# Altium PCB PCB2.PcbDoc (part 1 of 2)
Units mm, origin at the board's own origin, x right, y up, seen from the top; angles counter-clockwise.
Board outline 159.99 x 100 mm, 12 copper layers (TopLayer, VCC, GROUND, MidLayer1, MidLayer2, MidLayer3, MidLayer4, MidLayer5, MidLayer6, MidLayer7, MidLayer8, BottomLayer); 300 components, 468 nets, 2269 pads, 42 vias.
Unrouted connection lines stored in the file: 456.
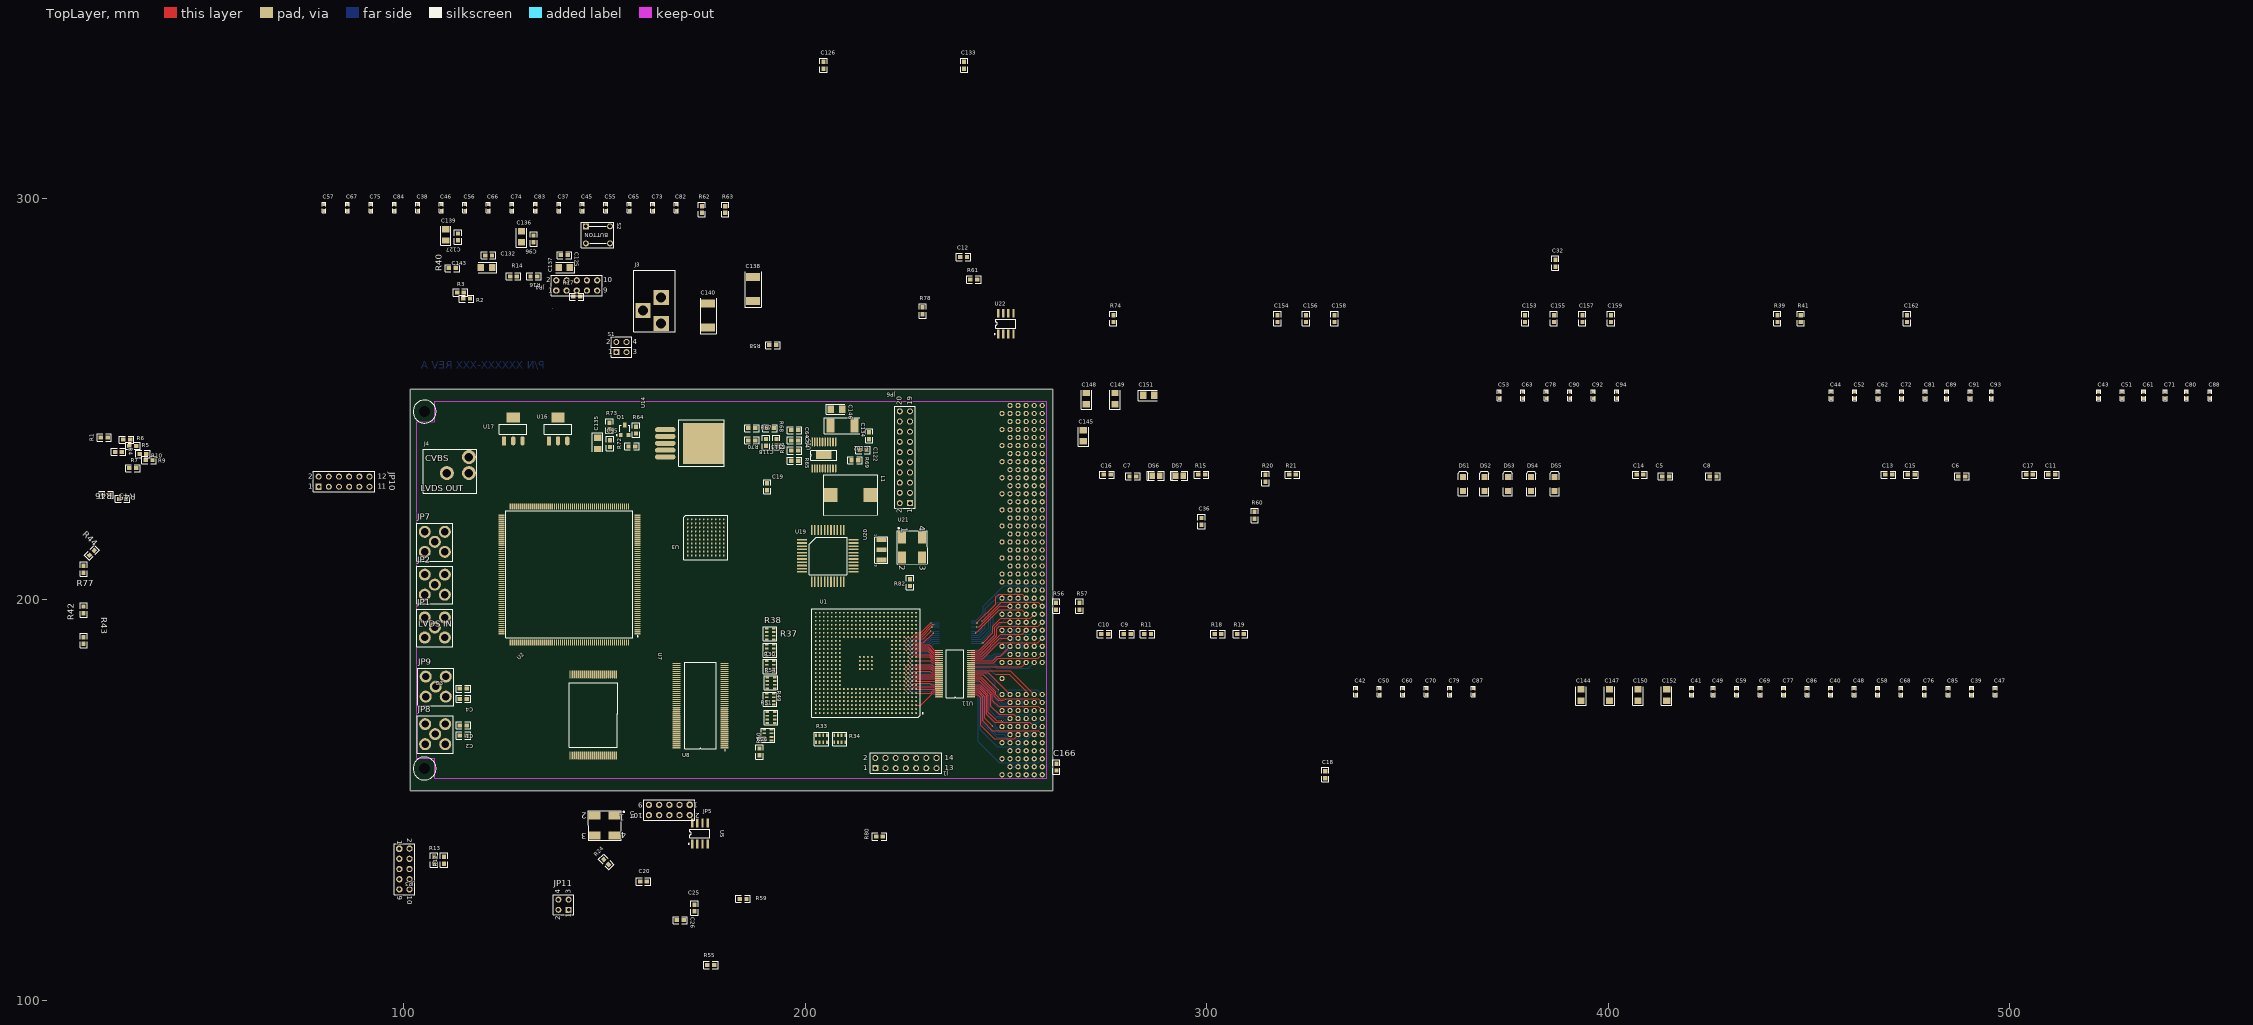
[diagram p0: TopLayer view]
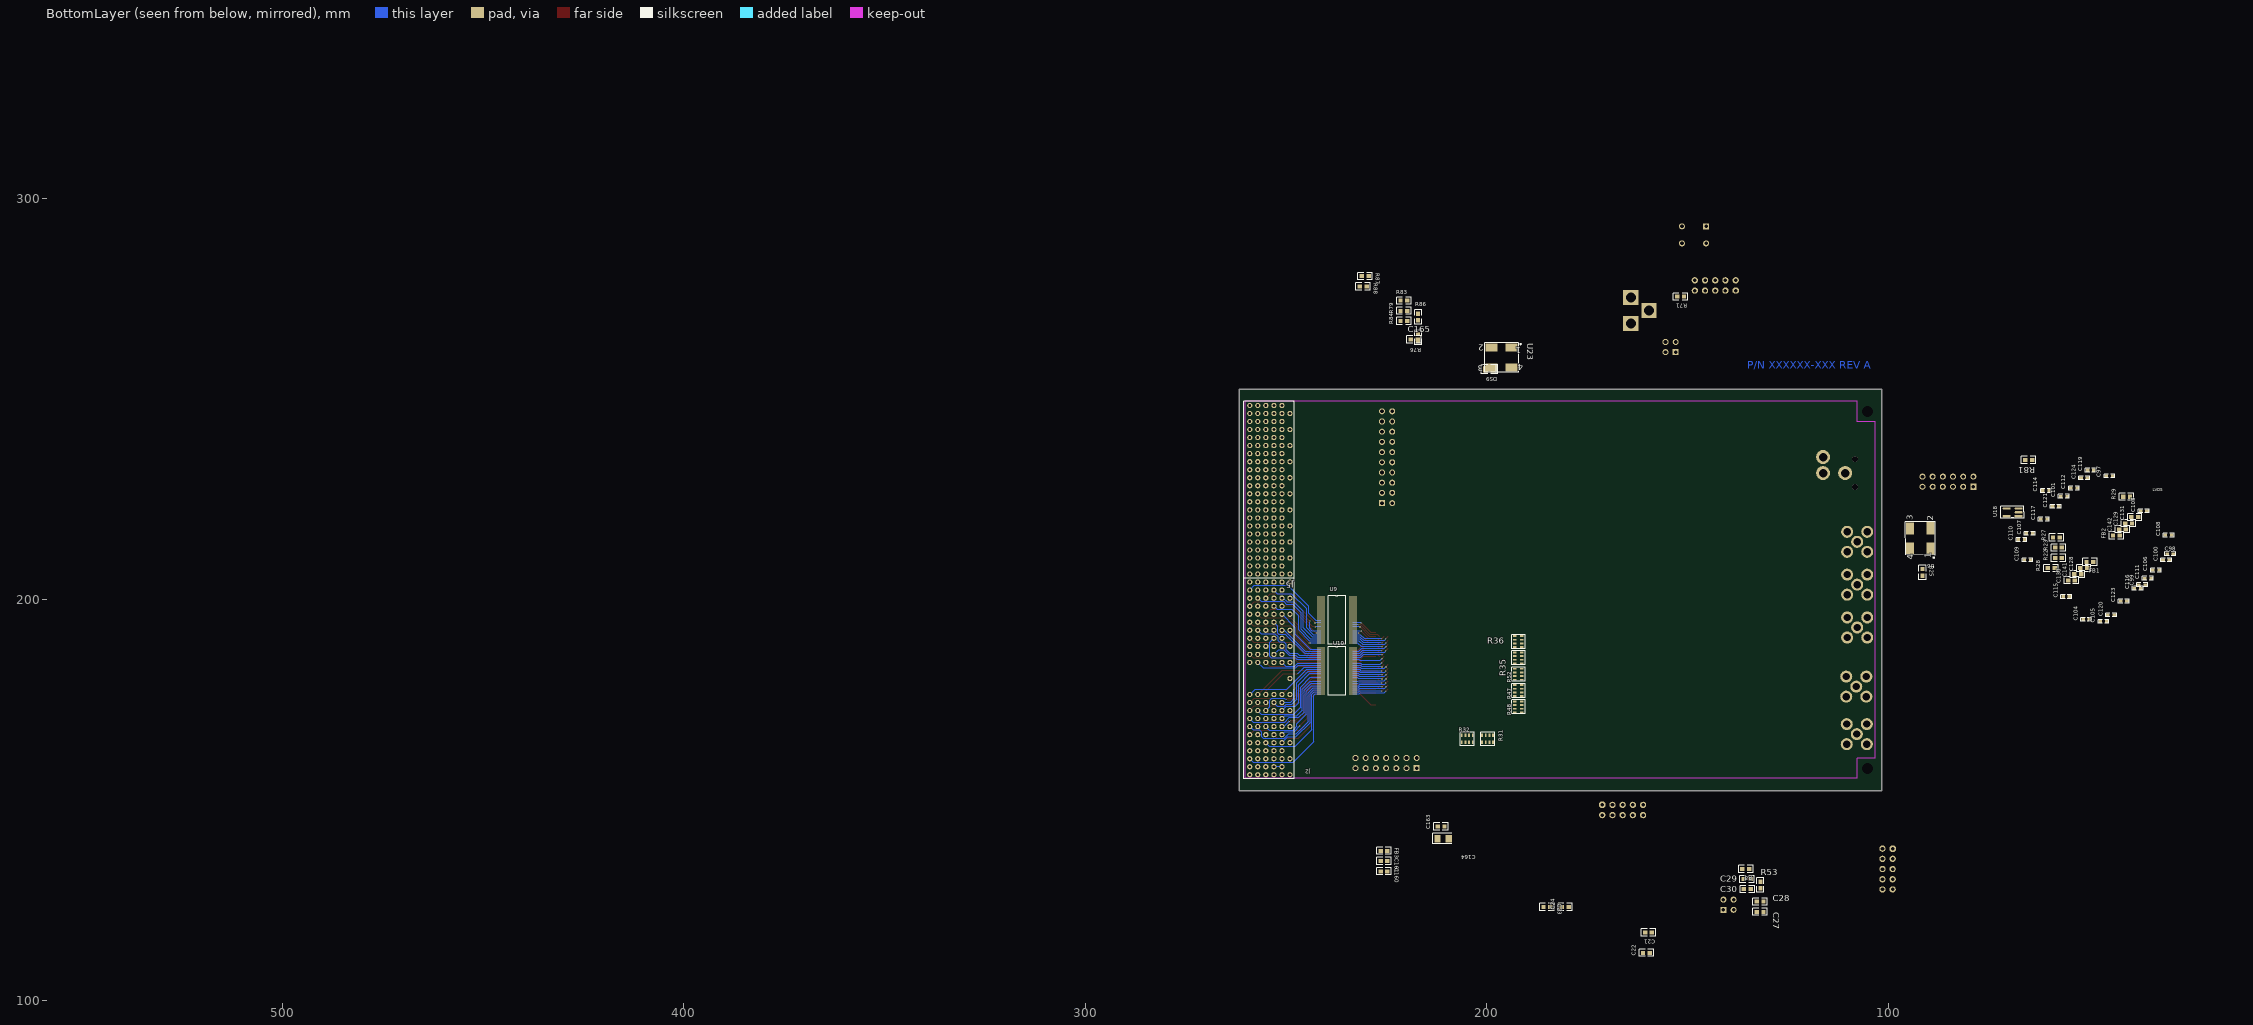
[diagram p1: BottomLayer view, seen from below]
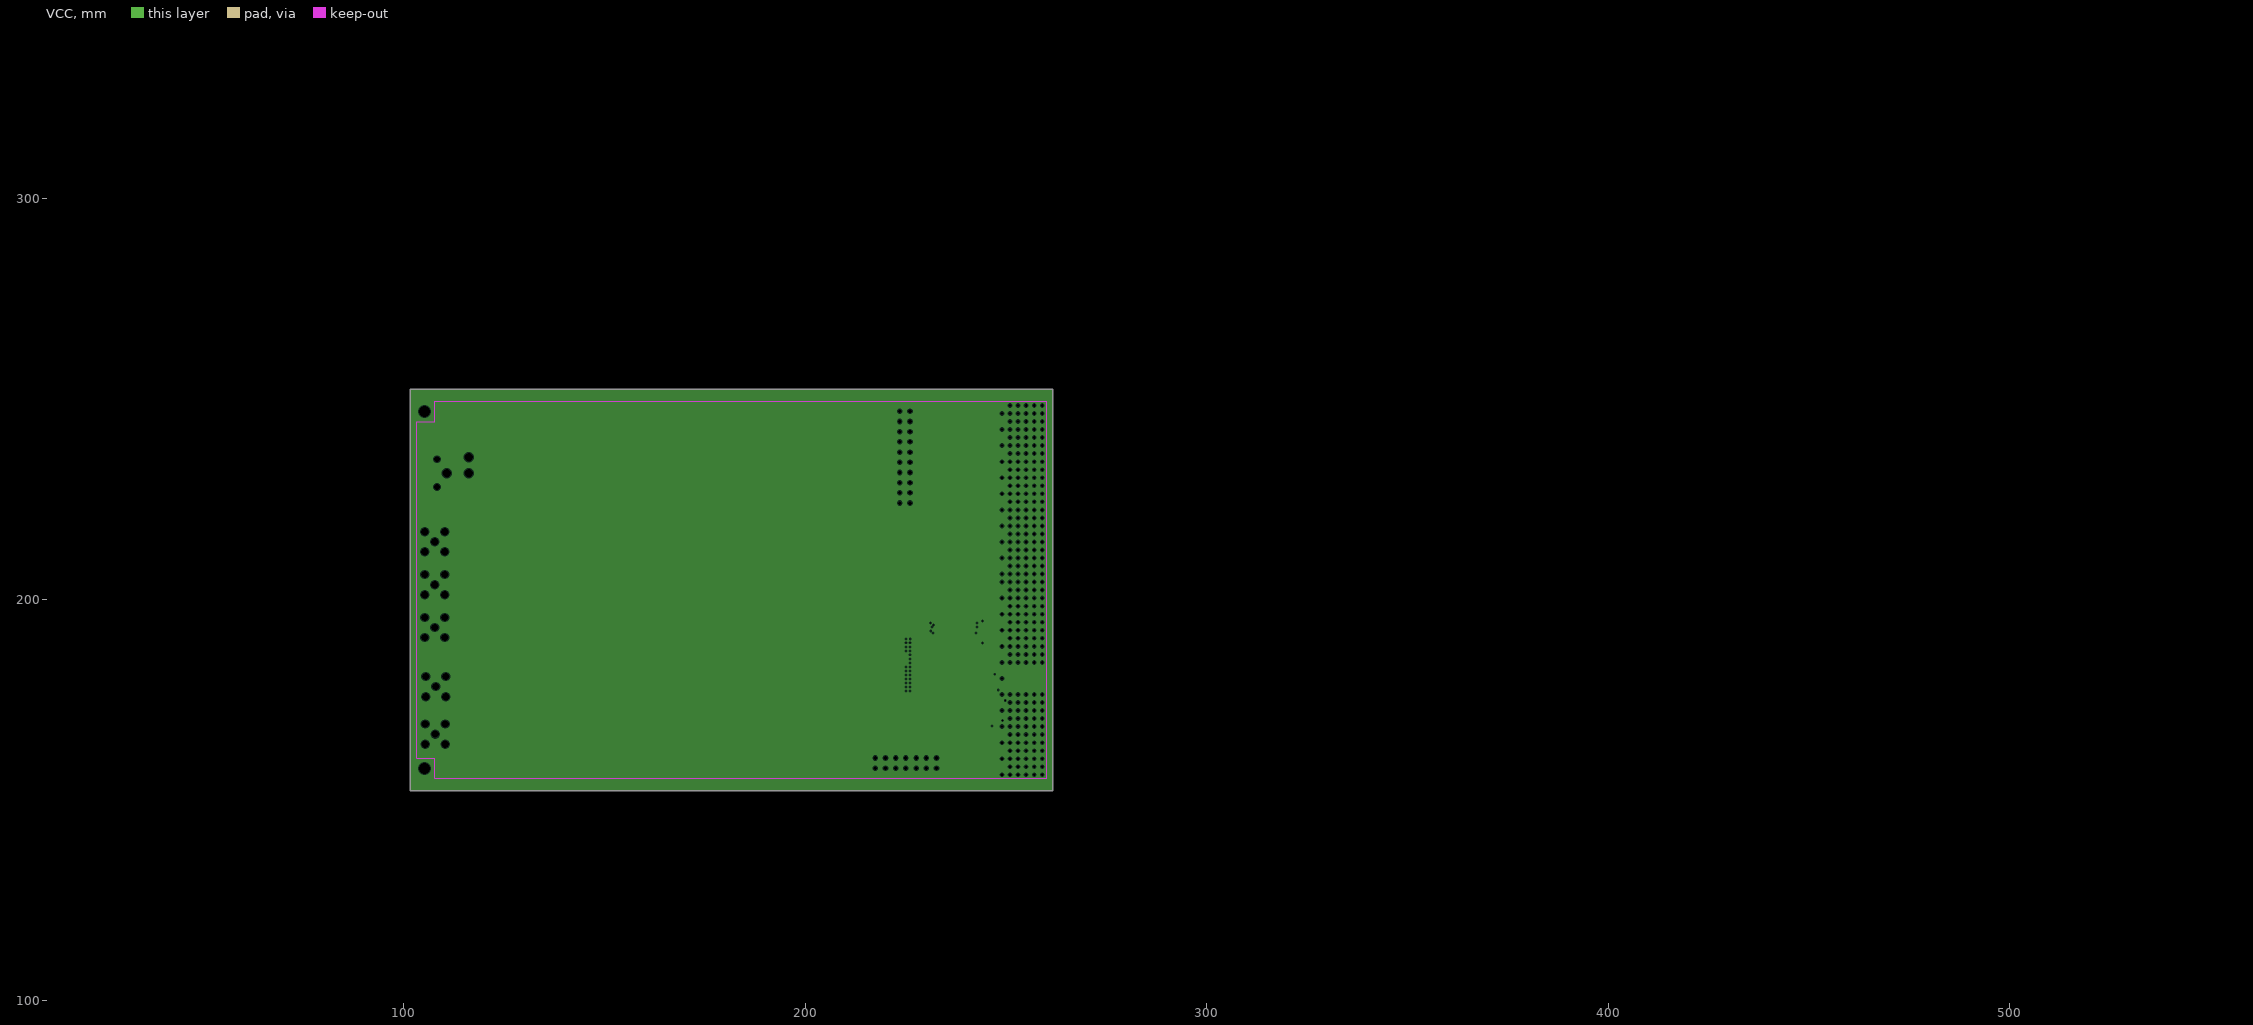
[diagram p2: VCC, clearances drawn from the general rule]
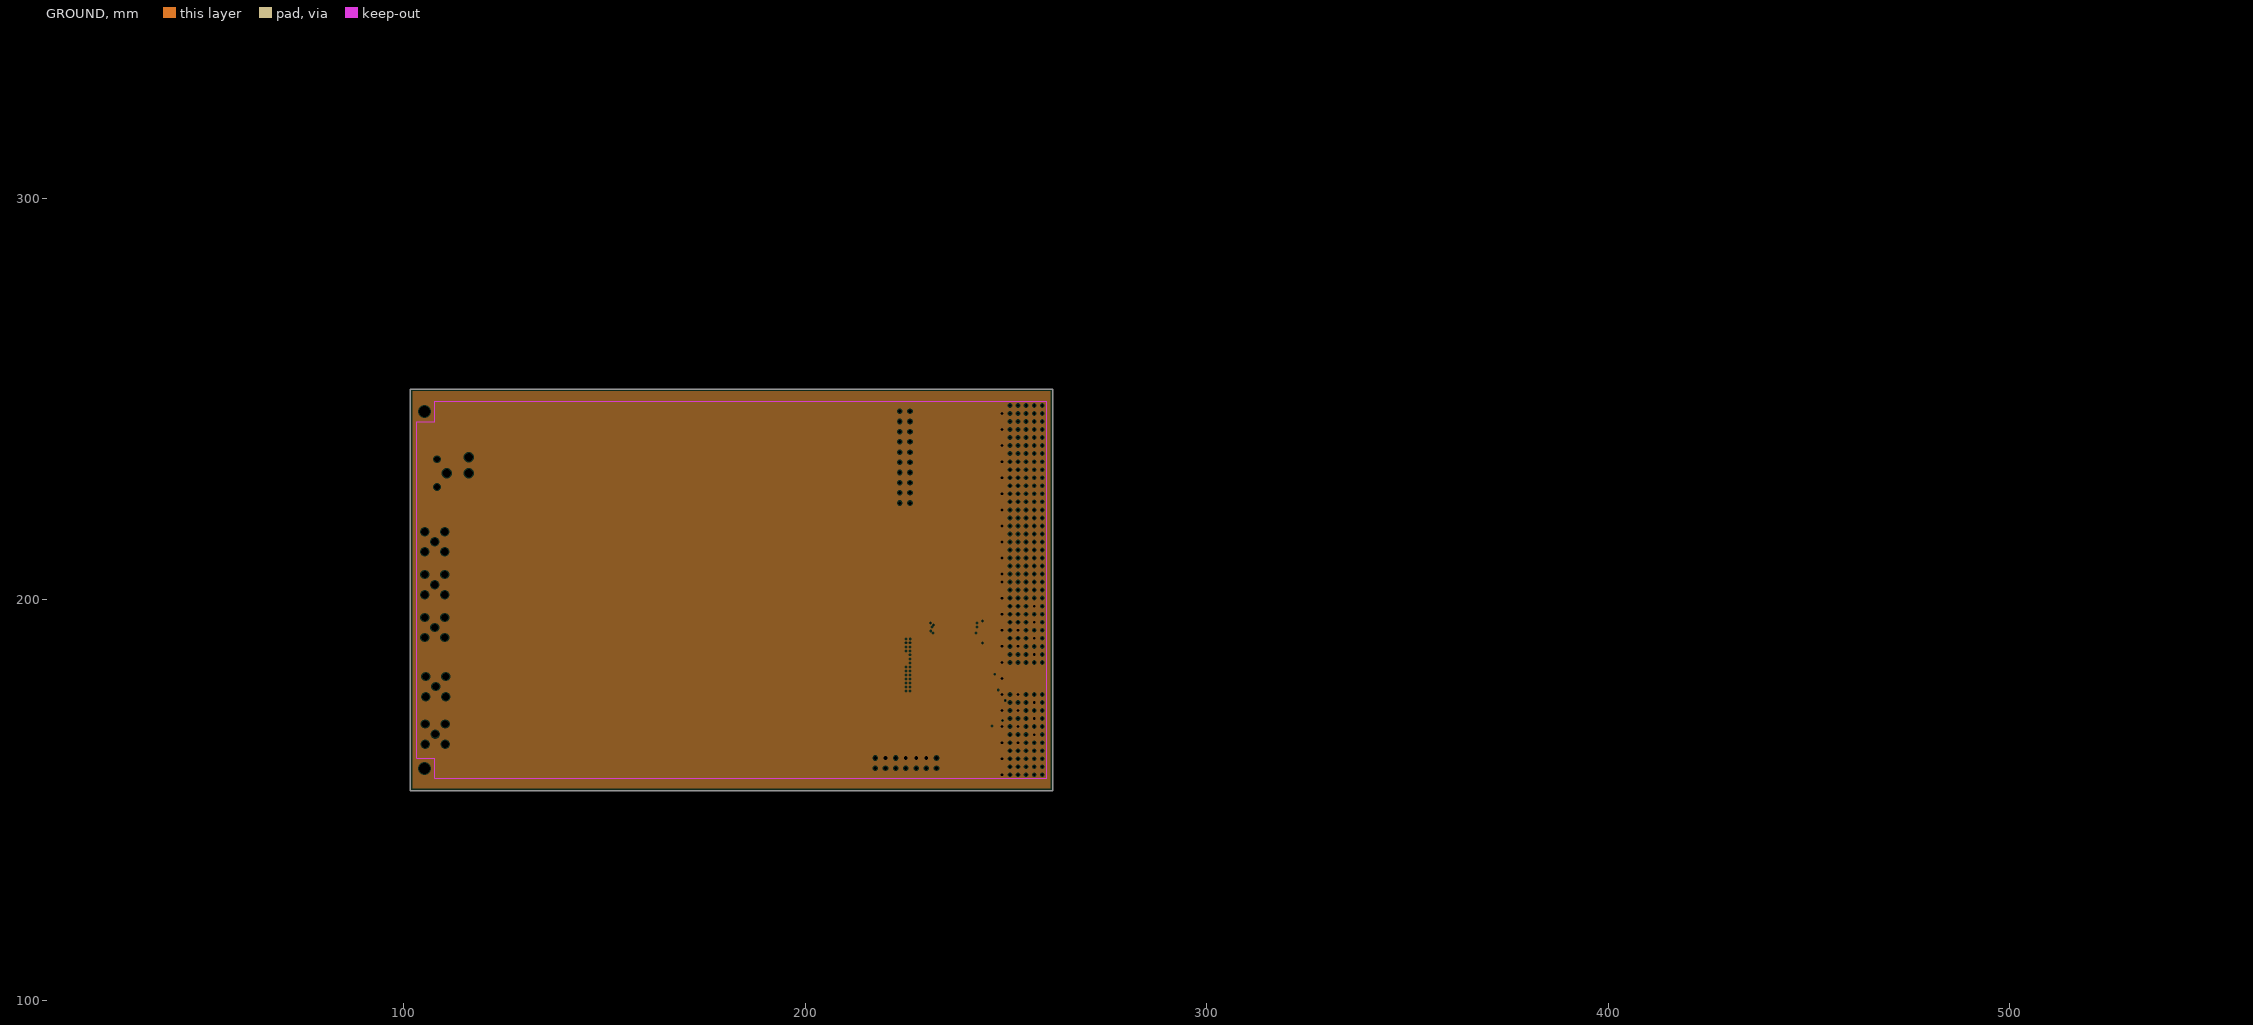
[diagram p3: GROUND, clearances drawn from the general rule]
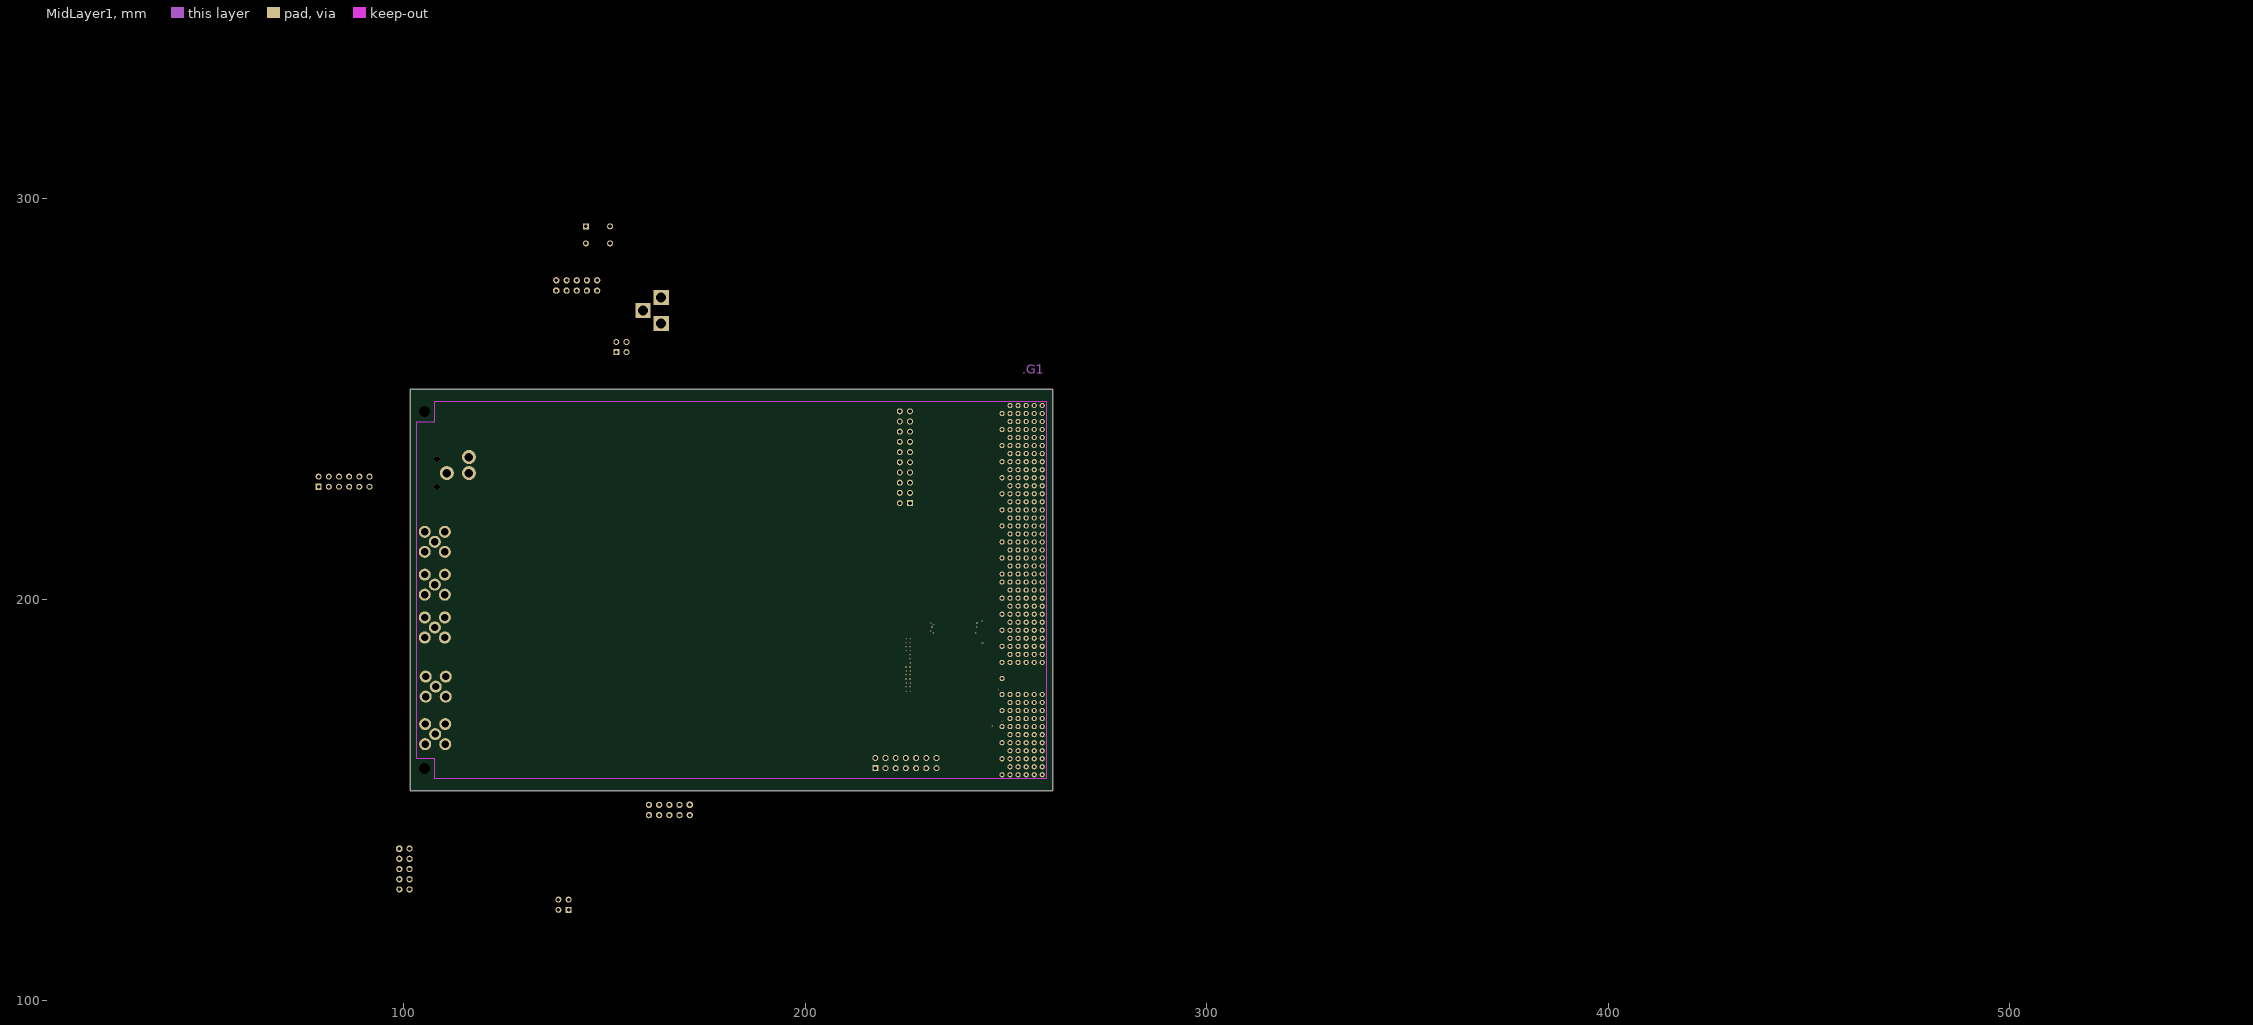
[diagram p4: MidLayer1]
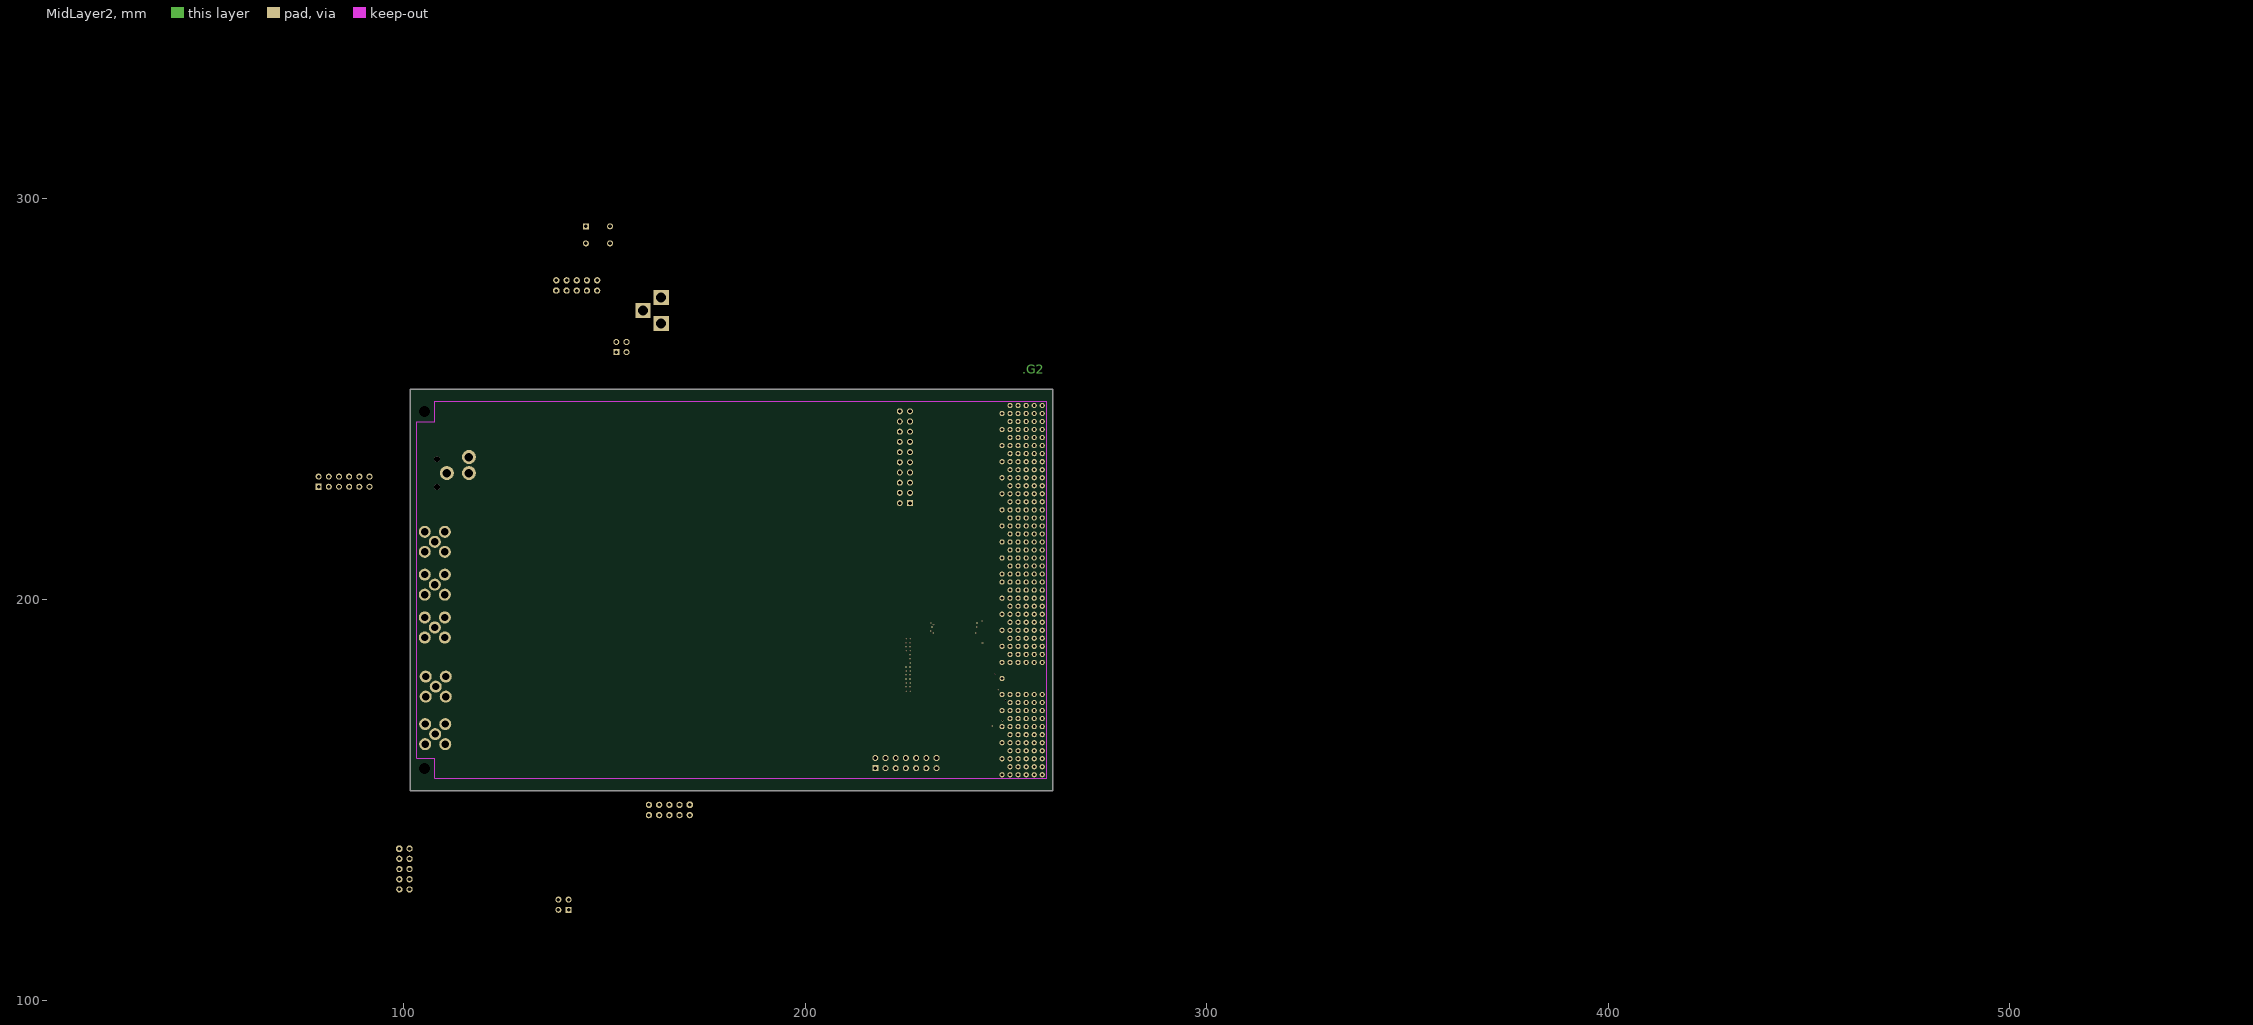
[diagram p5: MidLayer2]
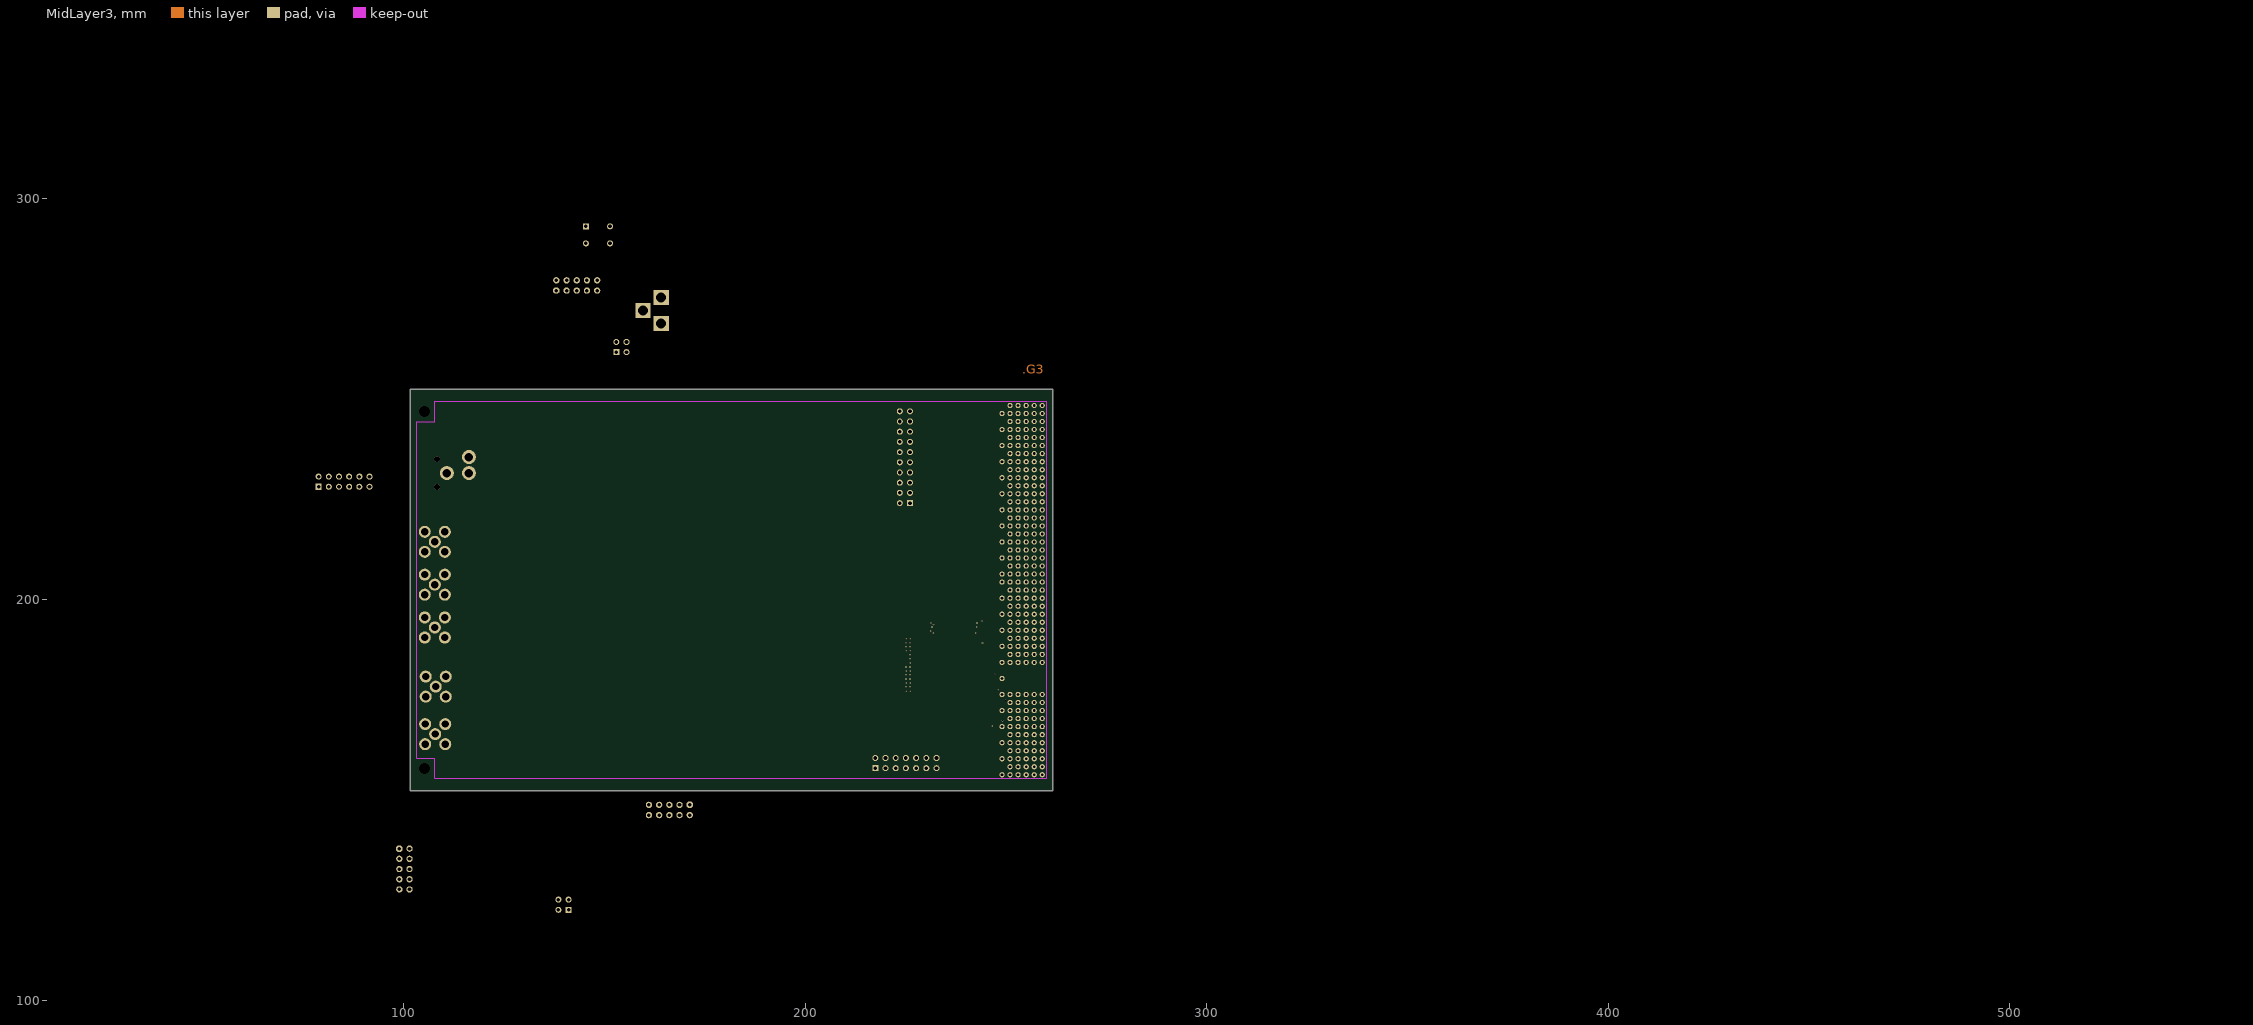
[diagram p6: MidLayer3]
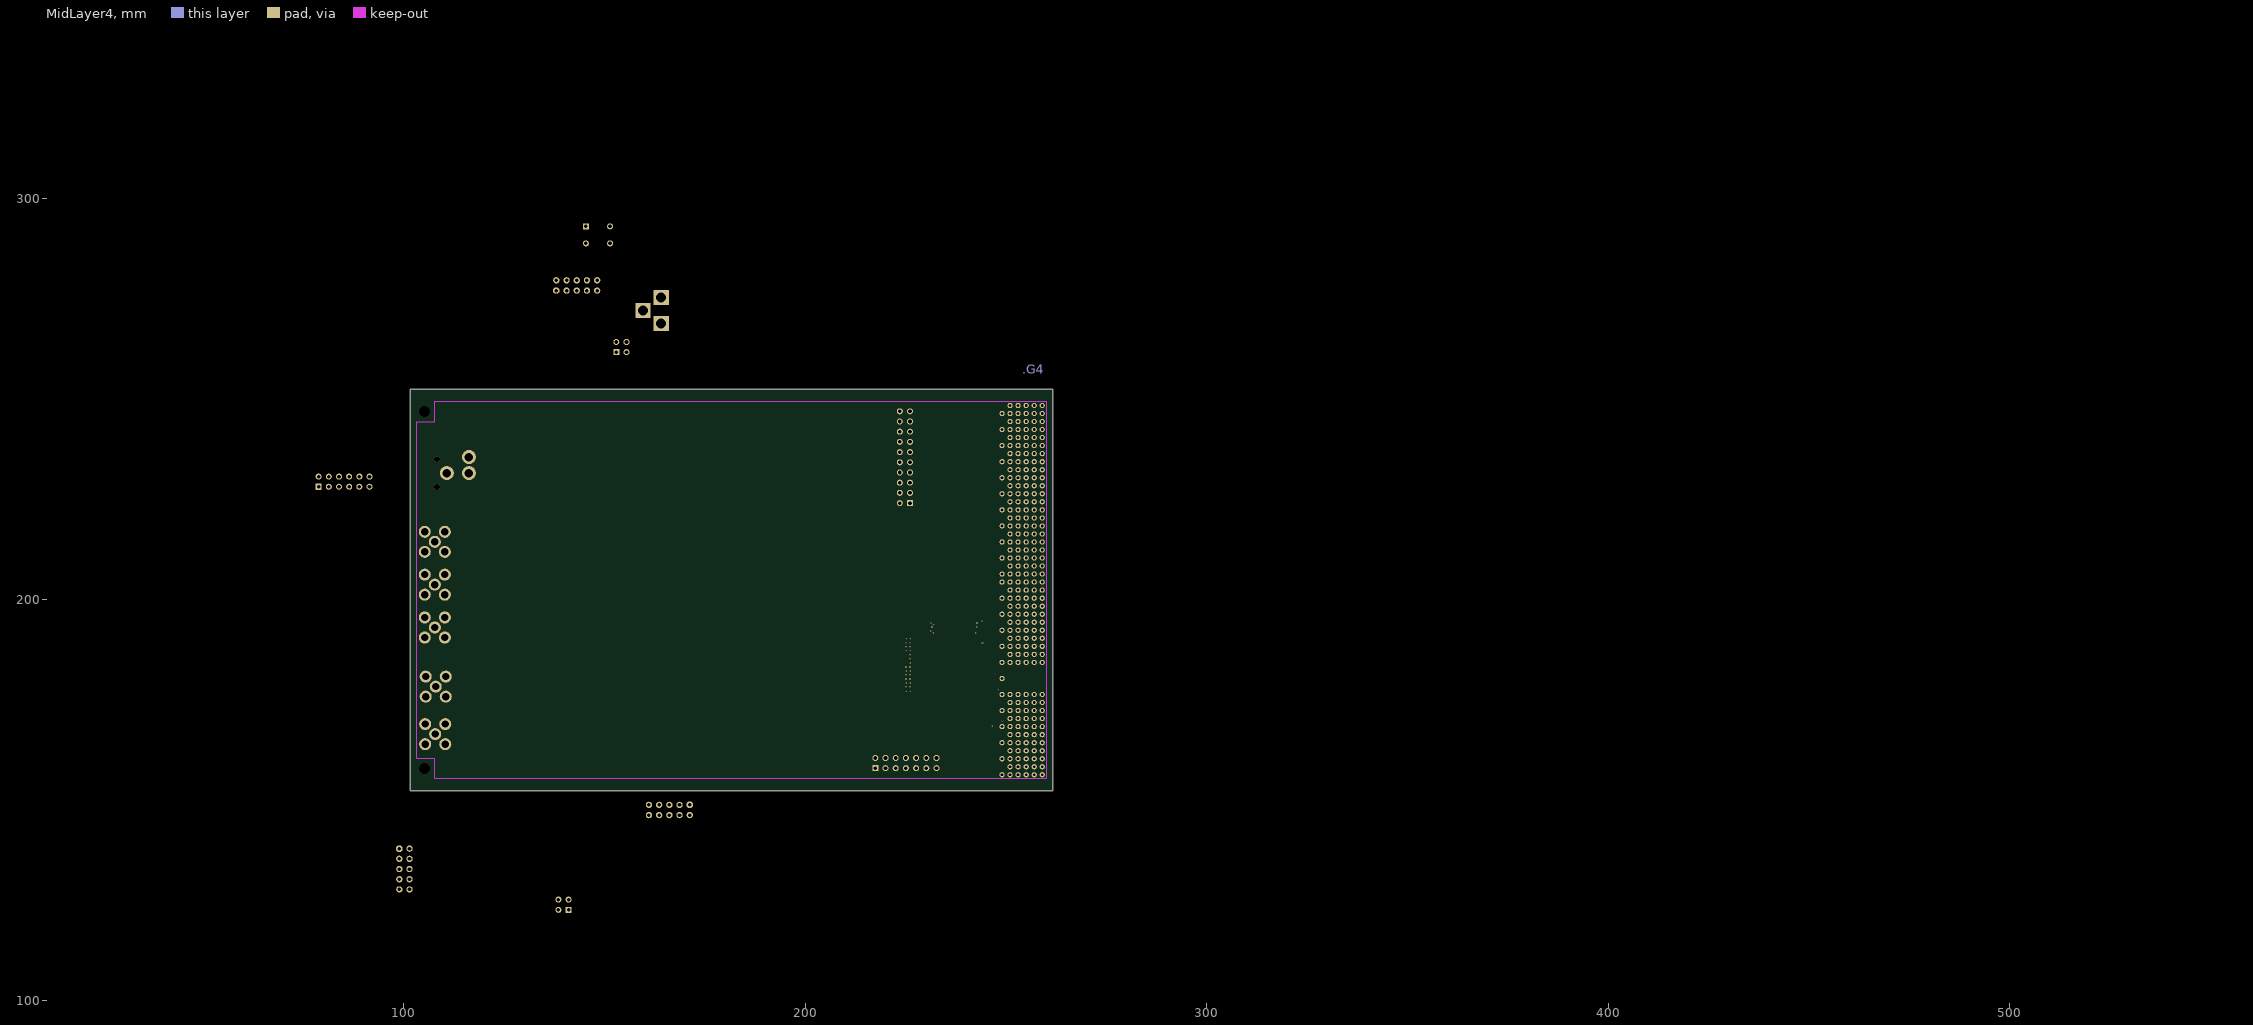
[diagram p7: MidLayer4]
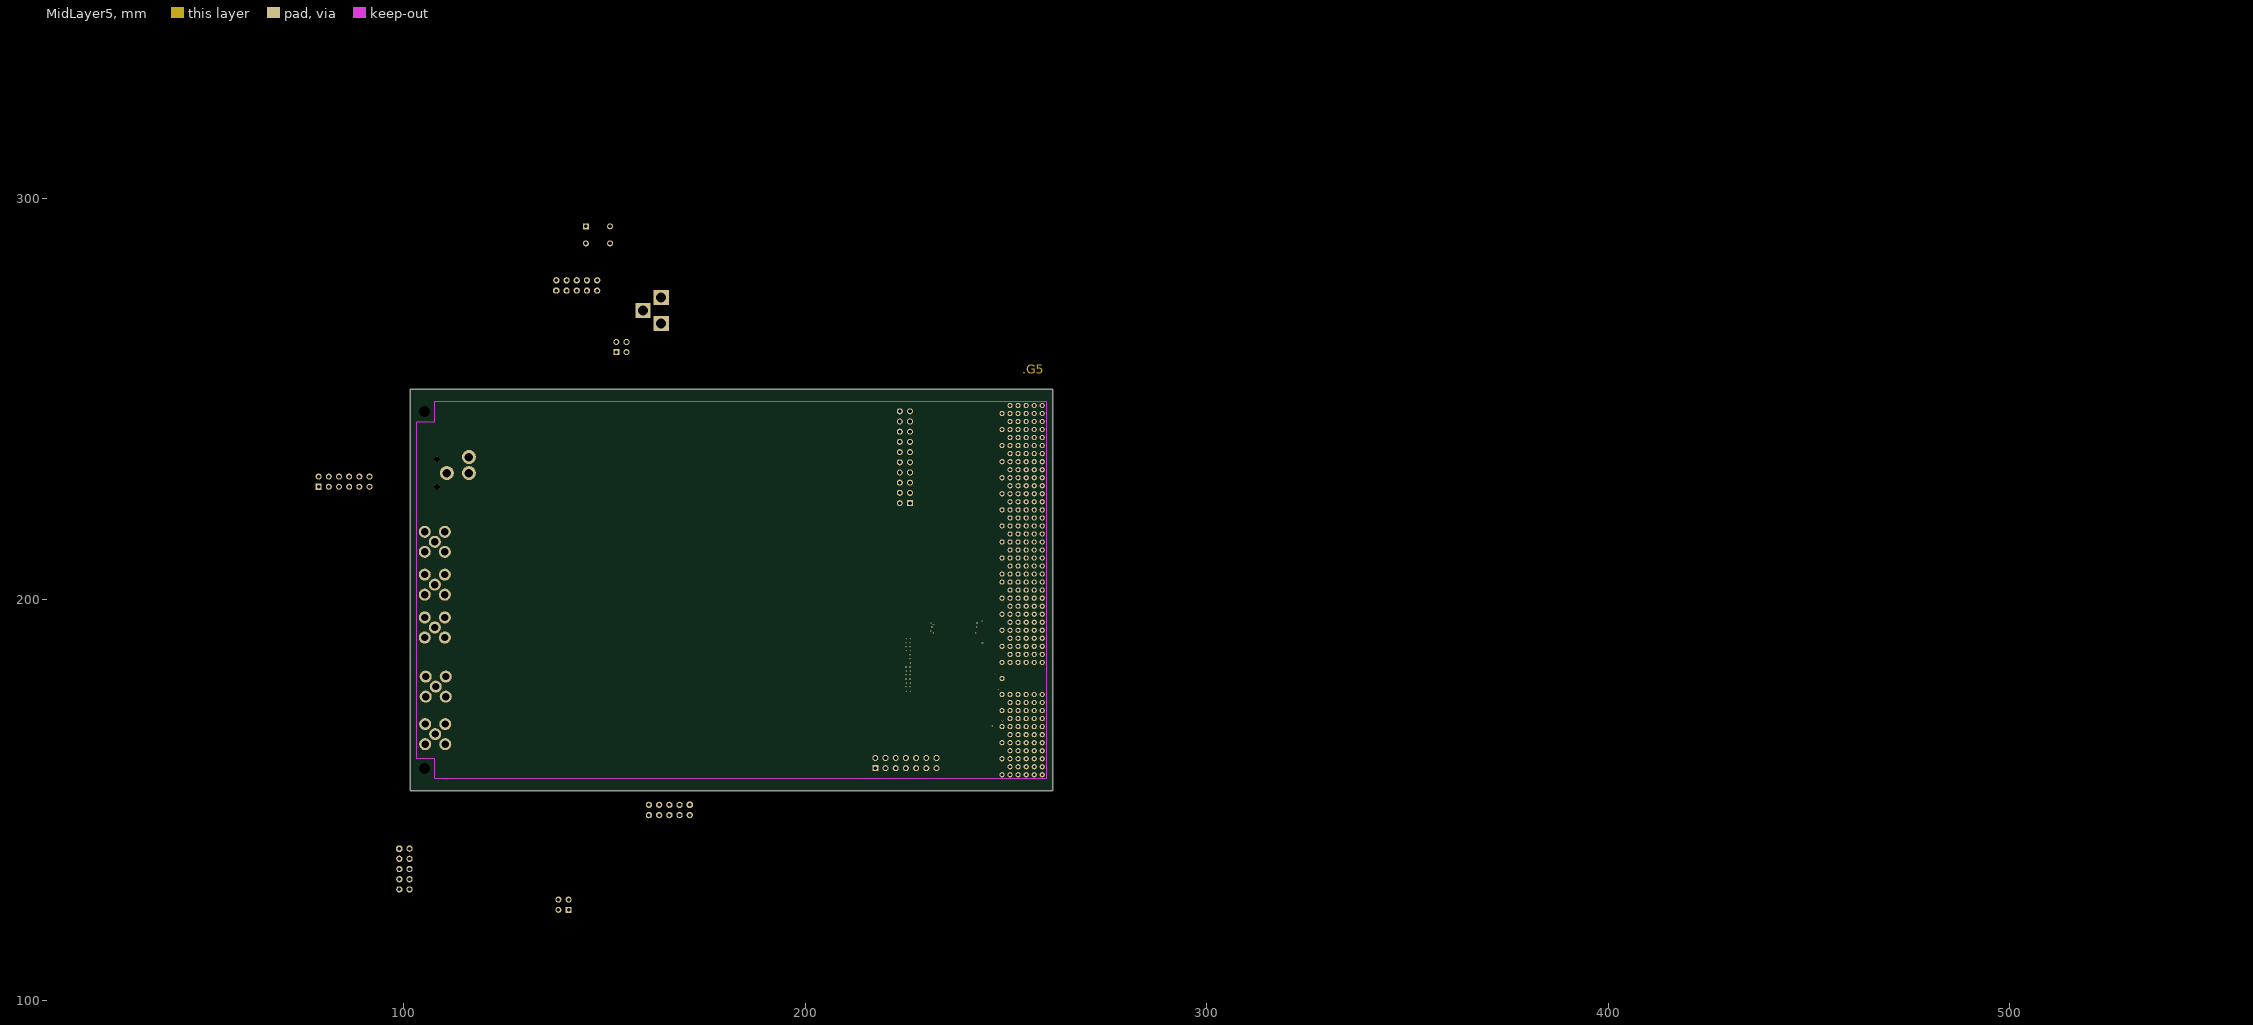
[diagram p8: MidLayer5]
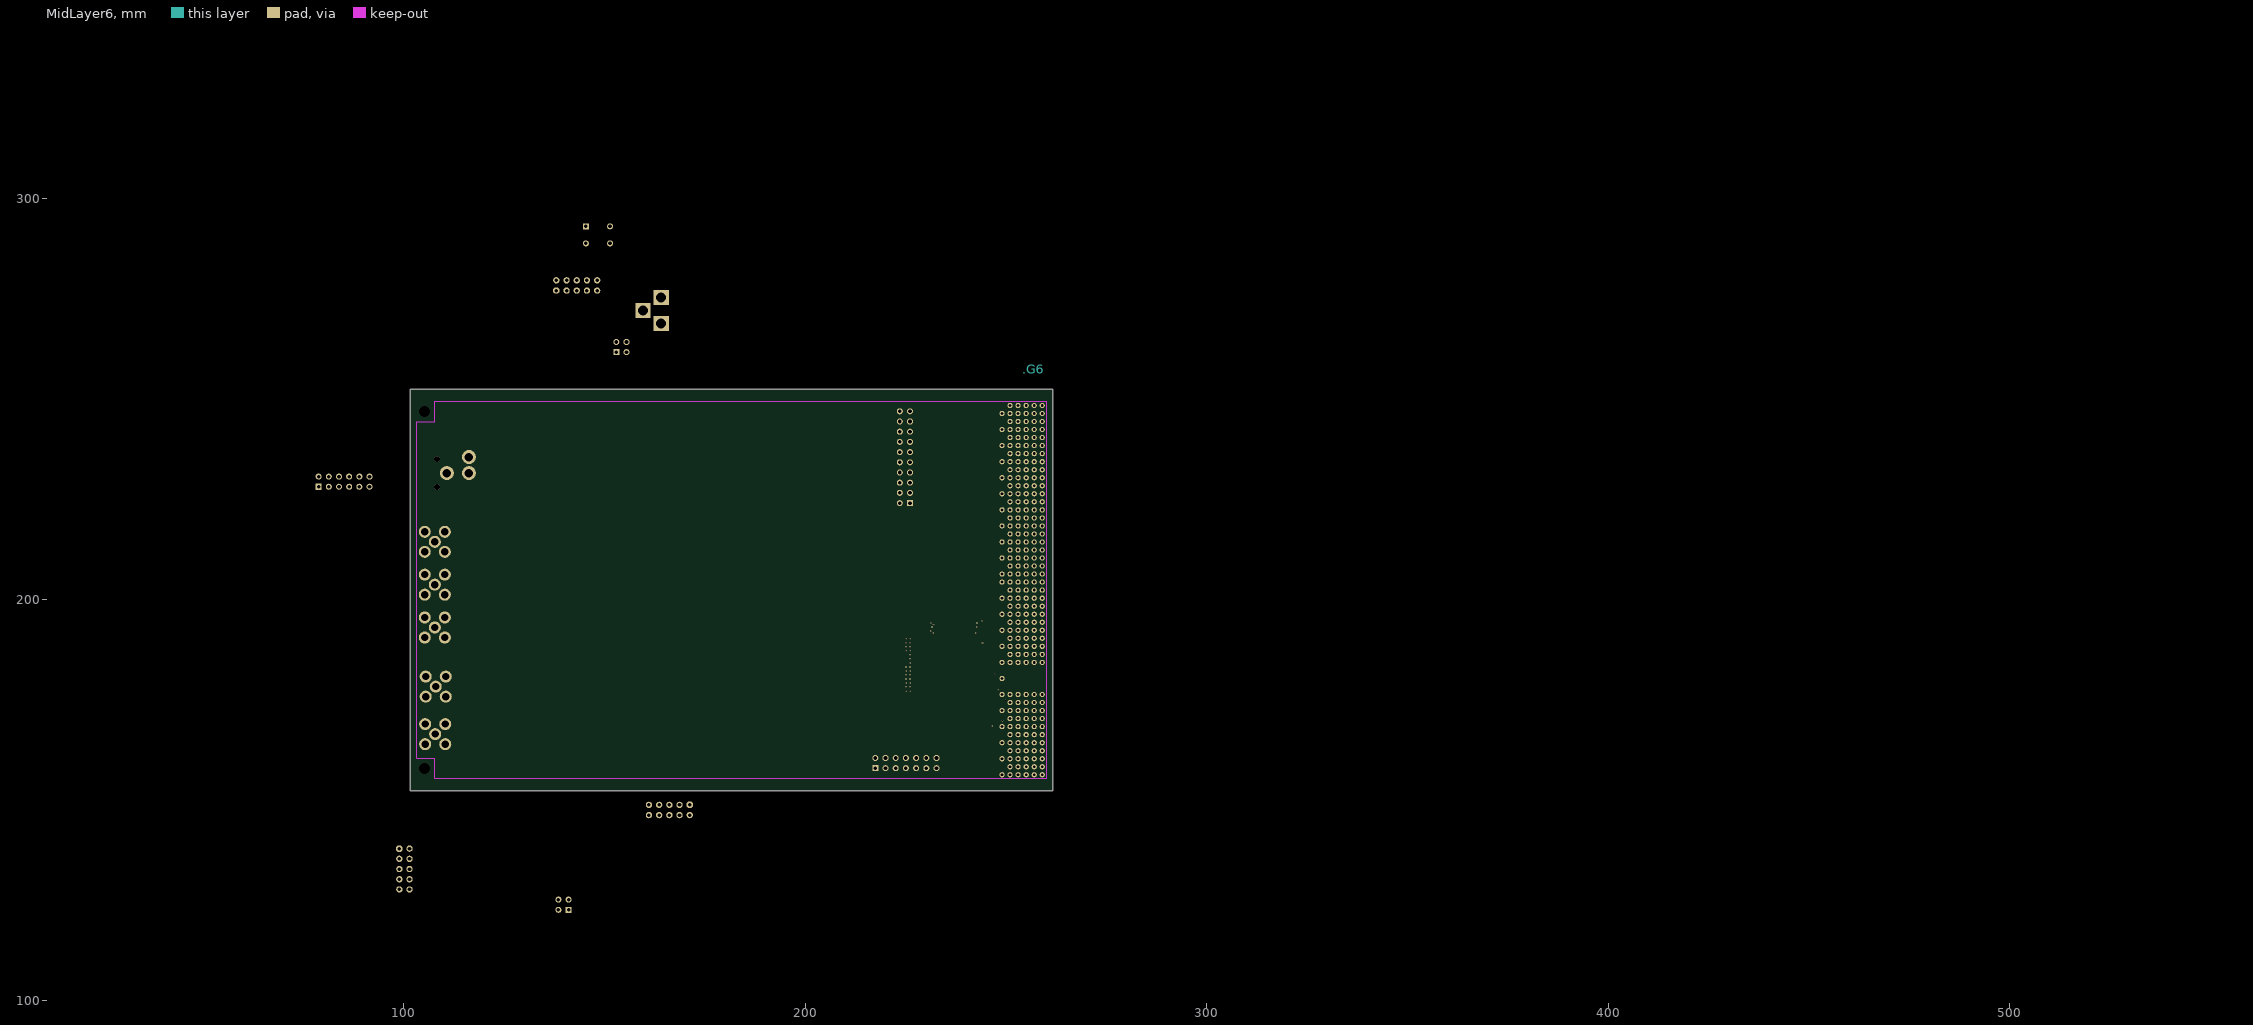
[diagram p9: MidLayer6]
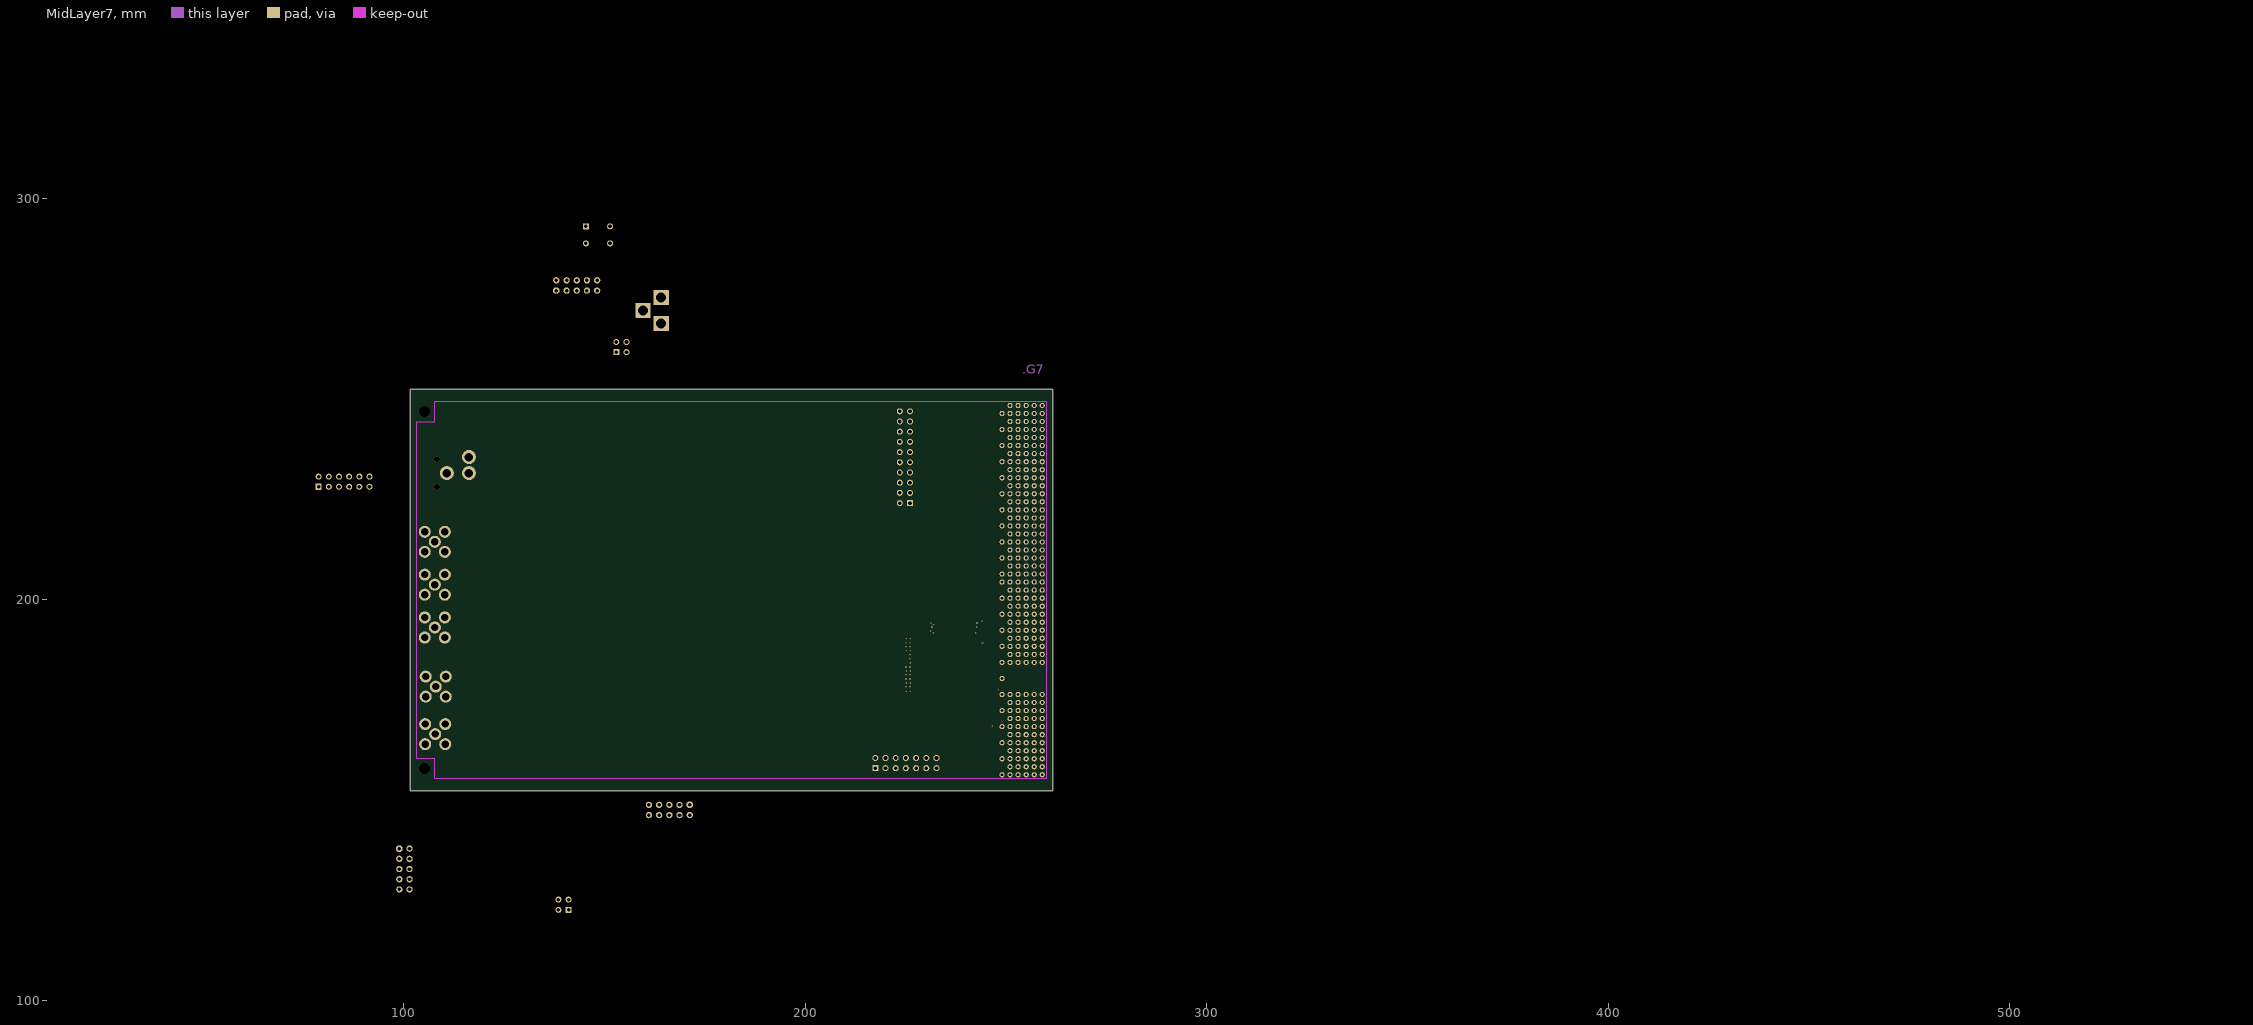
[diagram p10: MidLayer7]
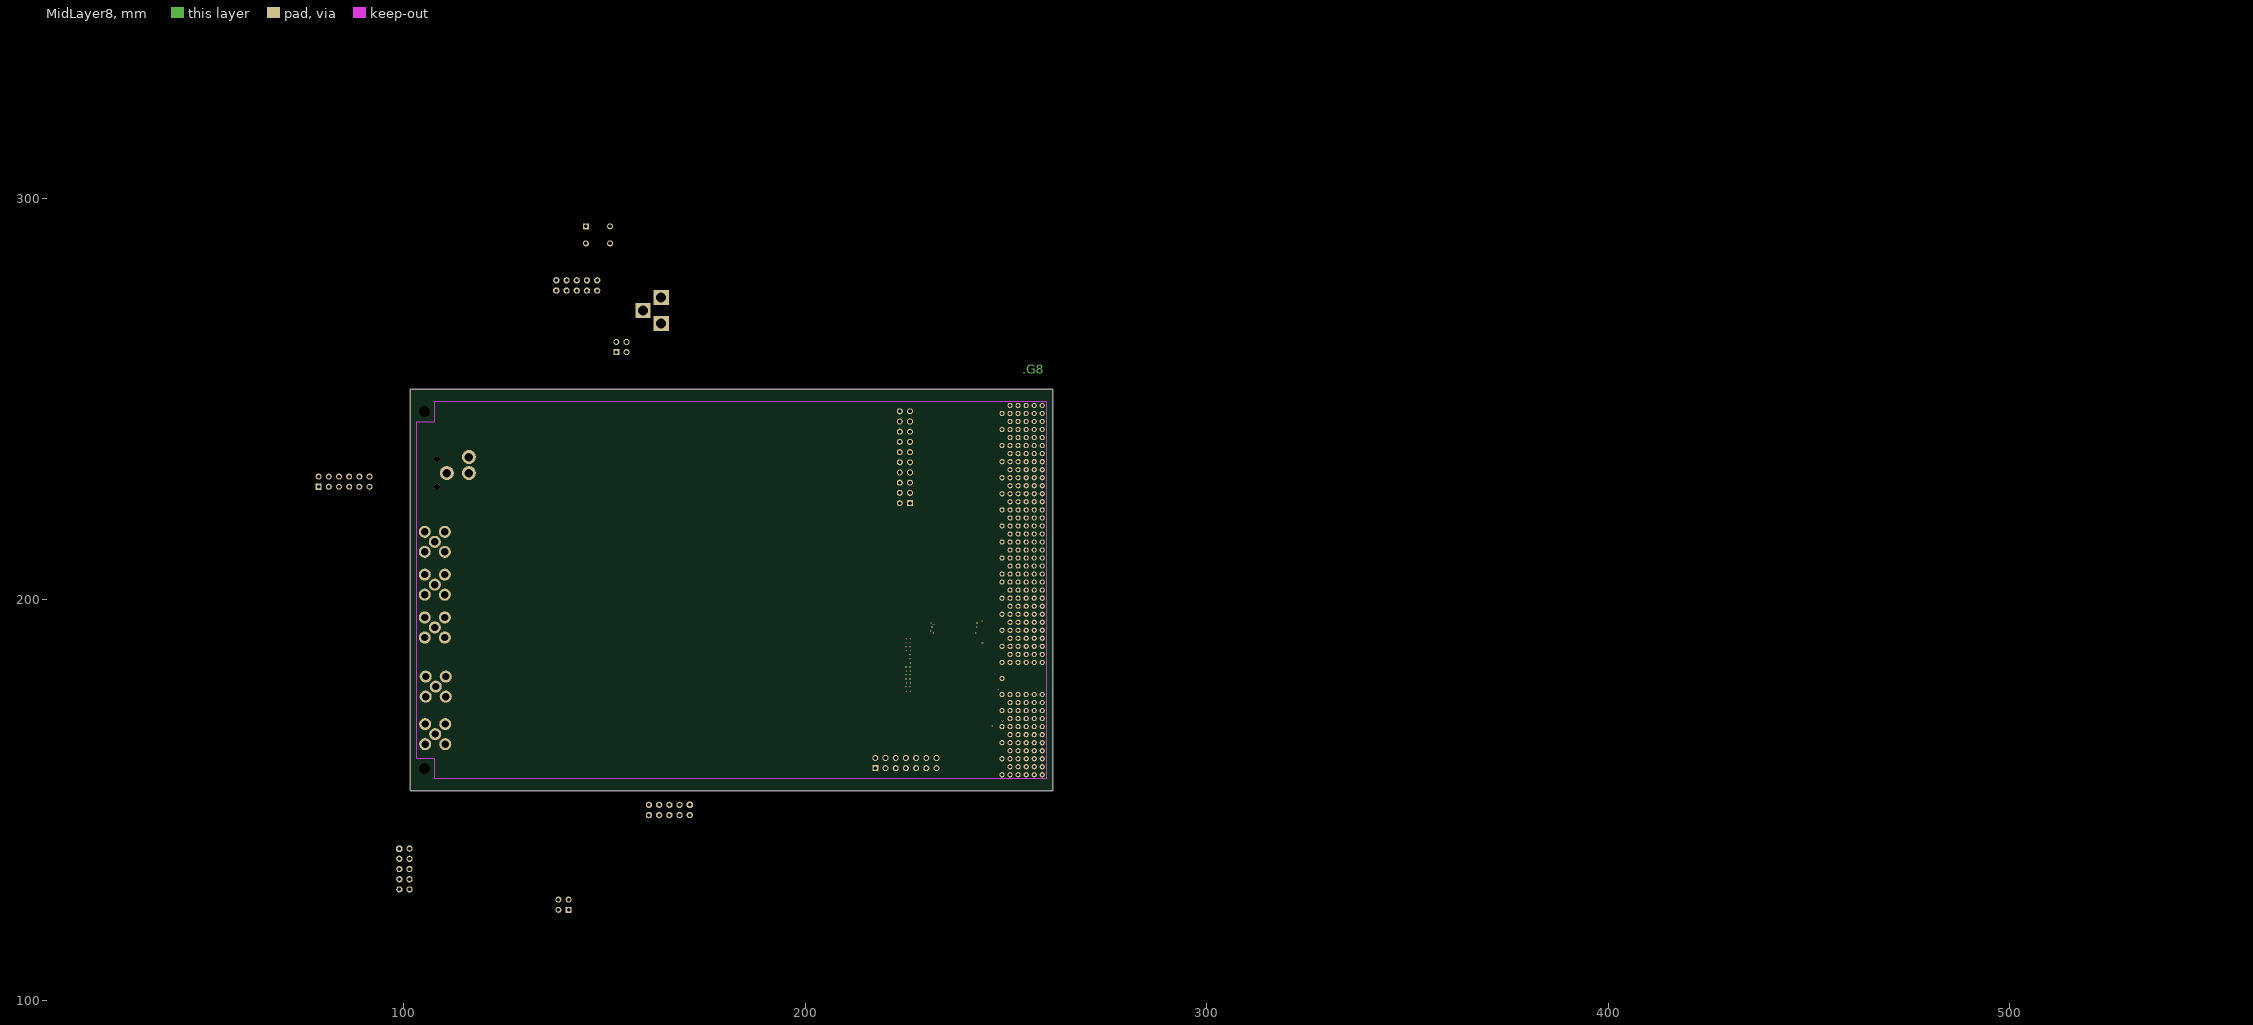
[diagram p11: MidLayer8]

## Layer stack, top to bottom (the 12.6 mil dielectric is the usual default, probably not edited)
TopLayer: signal copper 0.0356
Dielectric: core 0.32, FR-4, Dk 4.8
VCC: plane copper 0.0356
Dielectric: prepreg 0.32, FR-4, Dk 4.8
GROUND: plane copper 0.0356, net GND
Dielectric: core 0.32, FR-4, Dk 4.8
MidLayer1: signal copper 0.0356
Dielectric: prepreg 0.32, FR-4, Dk 4.8
MidLayer2: signal copper 0.0356
Dielectric: core 0.32, FR-4, Dk 4.8
MidLayer3: signal copper 0.0356
Dielectric: prepreg 0.32, FR-4, Dk 4.8
MidLayer4: signal copper 0.0356
Dielectric: core 0.32, FR-4, Dk 4.8
MidLayer5: signal copper 0.0356
Dielectric: prepreg 0.32, FR-4, Dk 4.8
MidLayer6: signal copper 0.0356
Dielectric: core 0.32, FR-4, Dk 4.8
MidLayer7: signal copper 0.0356
Dielectric: prepreg 0.32, FR-4, Dk 4.8
MidLayer8: signal copper 0.0356
Dielectric: core 0.32, FR-4, Dk 4.8
BottomLayer: signal copper 0.0356

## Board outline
101.6,152.4 261.595,152.4 261.595,252.4 101.6,252.4

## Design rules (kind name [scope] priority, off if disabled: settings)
Clearance [All] p1: gap=0.152
ComponentClearance ComponentClearance_1 [All] p1: gap=0.254 collisioncheckmode=0
HoleSize HoleSize_1 [All] p1: absolutevalues=TRUE maxlimit=2.54 minlimit=0.025 maxpercent=80.000 minpercent=20.000
LayerPairs LayerPairs_1 [All] p1: enforce=TRUE
PasteMaskExpansion PasteMaskExpansion_1 [All] p1: expansion=0
PlaneClearance PlaneClearance_1 [All] p1: clearance=0.254
PlaneConnect [All] p1: planeconnectstyle=Relief reliefexpansion=0.508 reliefentries=4 reliefconductorwidth=0.254 reliefairgap=0.254
PolygonConnect PolygonConnect_1 [All] p1: connectstyle=Relief reliefconductorwidth=0.254 reliefentries=4 polygonreliefangle="90 Angle"
RoutingLayers [All] p1: top layer=Horizontal mid layer 1="Not Used" mid layer 2="Not Used" mid layer 3="Not Used" mid layer 4="Not Used" mid layer 5="Not Used" mid layer 6="Not Used" mid layer 7="Not Used" mid layer 8="Not Used" bottom layer=Vertical
RoutingPriority RoutingPriority_1 [All] p1: routingpriority=0
RoutingTopology RoutingTopology_1 [All] p1: topology=Shortest
RoutingVias [All] p1: holewidth=0.203 width=0.406 viastyle="Through Hole" minholewidth=0.203 minwidth=0.406 maxholewidth=0.711 maxwidth=1.27
ShortCircuit ShortCircuit_1 [All] p1: allowed=FALSE
SolderMaskExpansion SolderMaskExpansion_1 [All] p1: expansion=0.051
TestPointUsage TestPointUsage_1 [All] p1: valid=0 allowmultiple=FALSE
Testpoint Testpoint_1 [All] p1: side=7 testpointundercomponent=TRUE minsize=1.016 maxsize=2.54 preferedsize=1.524 minholesize=0.508 maxholesize=1.016 preferedholesize=0.813 testpointgrid=0.025 style=1001 order=1234567890
UnRoutedNet UnRoutedNet_1 [All] p1:
Width [All] p1: maxlimit=1.016 minlimit=0.152 preferedwidth=0.152
7 further rules are at their usual default settings.

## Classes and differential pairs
component class U_Sheet1_FPGA2: C1 C2 C3 C4 C5 C6 C7 C8 C9 C10 C11 C12 C13 C14 C15 C16 C17 C18 C27 C28 C29 C30 DS1 DS2 DS3 DS4 DS5 JP1 JP2 JP3 JP4 JP5 JP7 JP8 JP9 JP10 JP11 L2 R1 R2 R3 R4 R5 R6 R7 R8 R9 R10 R11 R12 R13 R14 R15 R16 R17 R18 R19 R20 R21 R22 R23 R24 R25 R26 R27 R28 R29 R42 R43 R44 R45 R46 R53 R77 U2 U3 U4 U5 U6
component class U_Sheet2_DSP_EMIF: C19 C20 C21 C22 C23 C24 C25 C26 J1 R30 R31 R32 R33 R34 R35 R36 R37 R38 R47 R48 R49 R50 R51 R52 R54 R55 R56 R57 R58 R59 S1 U7 U8
component class U_Sheet2_PXI: C32 C36 C166 J2 J5 JP6 R60 R61 U9 U10 U11
component class U_Sheet3_power_clock: C37 C38 C39 C40 C41 C42 C43 C44 C45 C46 C47 C48 C49 C50 C51 C52 C53 C54 C55 C56 C57 C58 C59 C60 C61 C62 C63 C64 C65 C66 C67 C68 C69 C70 C71 C72 C73 C74 C75 C76 C77 C78 C79 C80 C81 C82 C83 C84 C85 C86 C87 C88 C89 C90 C91 C92 C93 C94 C95 C96 C97 C98 C99 C100 C101 C102 C103 C104 C105 C106 C107 C108 C109 C110 C111 C112 C113 C114 C115 C116 C117 C118 C119 C120 C121 C122 C123 C124 C125 C126 C127 C128 C129 C130 C131 C132 C134 C135 C136 C137 C138 C139 C140 C141 C142 C143 C144 C145 C146 C147 C148 C149 C150 C151 C152 DS6 DS7 FB1 FB2 J3 L1 Q1 R62 R63 R64 R65 R66 R67 R68 R69 R70 R72 R73 U14 U15 U16 U17
component class U_Sheet4_DSP2_videoport: C133 C153 C154 C155 C156 C157 C158 C159 C160 C161 C162 C163 C164 C165 DS9 FB3 J4 R39 R40 R41 R71 R74 R76 R78 R79 R80 R81 R82 R83 R84 R86 R87 R88 R? S2 U1 U18 U19 U20 U21 U22 U23

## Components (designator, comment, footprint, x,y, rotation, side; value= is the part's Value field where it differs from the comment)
C1 "Cap" C1608-0603 114.808,168.656 r180 top
C2 "Cap" C1608-0603 114.808,166.116 r180 top
C3 "Cap" C1608-0603 114.808,177.8 r180 top
C4 "Cap" C1608-0603 114.808,175.26 r180 top
C5 "Cap" C1608-0603 414.295,230.686 r0 top
C6 "Cap" C1608-0603 488.074,230.686 r0 top
C7 "Cap" C1608-0603 281.589,230.686 r0 top
C8 "Cap" C1608-0603 426.121,230.686 r0 top
C9 "Cap" C1608-0603 280.164,191.434 r0 top
C10 "Cap" C1608-0603 274.563,191.434 r0 top
C11 "Cap" C1608-0603 510.5,231.086 r0 top
C12 "Cap" C1608-0603 239.42,285.318 r0 top
C13 "Cap" C1608-0603 469.848,231.086 r0 top
C14 "Cap" C1608-0603 407.895,231.086 r0 top
C15 "Cap" C1608-0603 475.448,231.086 r0 top
C16 "Cap" C1608-0603 275.188,231.086 r0 top
C17 "Cap" C1608-0603 504.925,231.086 r0 top
C18 "Cap" C1608-0603 329.503,156.374 r90 top
C19 "Cap" C1608-0603 190.5,228.092 r270 top
C20 "Cap" C1608-0603 159.69,129.769 r0 top
C21 "Cap" C1608-0603 159.69,117.069 r0 bottom
C22 "Cap" C1608-0603 160.198,111.989 r0 bottom
C23 "Cap" C1608-0603 184.988,123.419 r180 bottom
C24 "Cap" C1608-0603 180.416,123.419 r0 bottom
C25 "Cap" C1608-0603 172.39,123.165 r90 top
C26 "Cap" C1608-0603 168.834,120.117 r0 top
C27 "Cap" C1608-0603 131.877,124.739 r180 bottom
C28 "Cap" C1608-0603 131.877,122.199 r180 bottom
C29 "Cap" C1608-0603 135.103,130.327 r0 bottom
C30 "Cap" C1608-0603 135.052,127.864 r0 bottom
C32 "Cap" C1608-0603 386.819,283.789 r90 top
C36 "Cap" C1608-0603 298.704,219.456 r90 top
C37 "Cap" 0603 138.616,296.874 r90 top
C38 "Cap" 0603 103.49,296.874 r90 top
C39 "Cap" 0603 490.511,176.3 r90 top
C40 "Cap" 0603 455.384,176.3 r90 top
C41 "Cap" 0603 420.782,176.3 r90 top
C42 "Cap" 0603 337.128,176.3 r90 top
C43 "Cap" 0603 522.15,250.112 r90 top
C44 "Cap" 0603 455.522,250.112 r90 top
C45 "Cap" 0603 144.467,296.874 r90 top
C46 "Cap" 0603 109.34,296.874 r90 top
C47 "Cap" 0603 496.361,176.3 r90 top
C48 "Cap" 0603 461.234,176.3 r90 top
C49 "Cap" 0603 426.133,176.3 r90 top
C50 "Cap" 0603 342.978,176.3 r90 top
C51 "Cap" 0603 528.001,250.112 r90 top
C52 "Cap" 0603 461.373,250.112 r90 top
C53 "Cap" 0603 372.868,250.112 r90 top
C54 "Cap" C1608-0603 197.333,239.649 r0 top
C55 "Cap" 0603 150.317,296.874 r90 top
C56 "Cap" 0603 115.19,296.874 r90 top
C57 "Cap" 0603 80.089,296.874 r90 top
C58 "Cap" 0603 467.085,176.3 r90 top
C59 "Cap" 0603 431.983,176.3 r90 top
C60 "Cap" 0603 348.829,176.3 r90 top
C61 "Cap" 0603 533.351,250.112 r90 top
C62 "Cap" 0603 467.223,250.112 r90 top
C63 "Cap" 0603 378.718,250.112 r90 top
C64 "Cap" C1608-0603 197.333,242.189 r0 top
C65 "Cap" 0603 156.167,296.874 r90 top
C66 "Cap" 0603 121.041,296.874 r90 top
C67 "Cap" 0603 85.939,296.874 r90 top
C68 "Cap" 0603 472.935,176.3 r90 top
C69 "Cap" 0603 437.833,176.3 r90 top
C70 "Cap" 0603 354.679,176.3 r90 top
C71 "Cap" 0603 538.701,250.112 r90 top
C72 "Cap" 0603 473.073,250.112 r90 top
C73 "Cap" 0603 162.018,296.874 r90 top
C74 "Cap" 0603 126.916,296.874 r90 top
C75 "Cap" 0603 91.789,296.874 r90 top
C76 "Cap" 0603 478.785,176.3 r90 top
C77 "Cap" 0603 443.683,176.3 r90 top
C78 "Cap" 0603 384.569,250.112 r90 top
C79 "Cap" 0603 360.529,176.3 r90 top
C80 "Cap" 0603 544.027,250.112 r90 top
C81 "Cap" 0603 478.923,250.112 r90 top
C82 "Cap" 0603 167.868,296.874 r90 top
C83 "Cap" 0603 132.766,296.874 r90 top
C84 "Cap" 0603 97.639,296.874 r90 top
C85 "Cap" 0603 484.66,176.3 r90 top
C86 "Cap" 0603 449.534,176.3 r90 top
C87 "Cap" 0603 366.38,176.3 r90 top
C88 "Cap" 0603 549.902,250.112 r90 top
C89 "Cap" 0603 484.274,250.112 r90 top
C90 "Cap" 0603 390.419,250.112 r90 top
C91 "Cap" 0603 490.124,250.112 r90 top
C92 "Cap" 0603 396.294,250.112 r90 top
C93 "Cap" 0603 495.474,250.112 r90 top
C94 "Cap" 0603 402.145,250.112 r90 top
C95 "Cap" C1608-0603 151.308,238.836 r90 top
C96 "Cap" C1608-0603 132.334,289.839 r270 top
C97 "Cap" 0603 44.048,230.78 r0 bottom
C98 "Cap" 0603 28.905,211.379 r0 bottom
C99 "Cap" 0603 35.92,203.661 r0 bottom
C100 "Cap" 0603 29.921,209.855 r0 bottom
C101 "Cap" 0603 55.419,225.7 r0 bottom
C102 "Cap" C1608-0603 215.9,240.792 r90 top
C103 "Cap" 0603 35.509,222.047 r0 bottom
C104 "Cap" 0603 49.831,195.025 r0 bottom
C105 "Cap" 0603 45.572,194.517 r0 bottom
C106 "Cap" 0603 32.461,207.315 r0 bottom
C107 "Cap" 0603 63.957,216.459 r0 bottom
C108 "Cap" 0603 29.316,216.048 r0 bottom
C109 "Cap" 0603 64.465,209.855 r0 bottom
C110 "Cap" 0603 65.989,214.935 r0 bottom
C111 "Cap" 0603 34.493,205.283 r0 bottom
C112 "Cap" 0603 52.879,227.732 r0 bottom
C113 "Cap" C1608-0603 192.761,239.141 r270 top
C114 "Cap" 0603 59.893,227.127 r0 bottom
C115 "Cap" 0603 54.813,200.711 r0 bottom
C116 "Cap" 0603 37.033,202.794 r0 bottom
C117 "Cap" 0603 60.401,220.015 r0 bottom
C118 "Cap" C1608-0603 190.221,239.141 r270 top
C119 "Cap" 0603 48.717,232.207 r0 bottom
C120 "Cap" 0603 43.637,196.139 r0 bottom
C121 "Cap" 0603 57.451,223.16 r0 bottom
C122 "Cap" C1608-0603 214.376,237.236 r0 top
C123 "Cap" 0603 40.492,199.597 r0 bottom
C124 "Cap" 0603 50.339,230.272 r0 bottom
C125 "Cap" C1608-0603 139.954,285.775 r0 top
C126 "Cap" C1608-0603 204.533,333.09 r90 top
C127 "Cap" C1608-0603 113.462,290.322 r270 top
C128 "Cap" C1608-0603 51.257,207.823 r0 bottom
C129 "Cap" C1608-0603 40.081,218.999 r0 bottom
C130 "Cap" C1608-0603 54.305,204.775 r0 bottom
C131 "Cap" C1608-0603 38.557,220.523 r0 bottom
C132 "Cap" C1608-0603 121.082,285.75 r0 top
C133 "Cap" C1608-0603 239.56,333.09 r90 top
C134 "Cap Pol1" CC6032 206.248,243.332 r0 top
C135 "Cap Pol1" CC3216-1206 148.26,238.895 r270 top
C136 "Cap Pol1" CC3216-1206 129.286,290.347 r90 top
C137 "Cap Pol1" CC3216-1206 139.954,282.727 r180 top
C138 "Cap Pol1" CC6032 186.944,274.32 r90 top
C139 "Cap Pol1" CC3216-1206 110.414,290.83 r90 top
C140 "Cap Pol1" CC6032 175.768,267.716 r90 top
C141 "Cap Pol1" C1608-0603 52.781,206.299 r0 bottom
C142 "Cap Pol1" C1608-0603 41.605,217.475 r0 bottom
C143 "Cap Pol1" CC3216-1206 120.574,282.702 r180 top
C144 "Cap Pol2" CC3216-1206 393.206,176.225 r90 top
C145 "Cap Pol2" CC3216-1206 269.24,240.792 r90 top
C146 "Cap Pol2" CC3216-1206 207.772,247.396 r0 top
C147 "Cap Pol2" CC3216-1206 400.331,176.225 r90 top
C148 "Cap Pol2" CC3216-1206 269.988,250.037 r90 top
C149 "Cap Pol2" CC3216-1206 277.114,250.037 r90 top
C150 "Cap Pol2" CC3216-1206 407.432,176.225 r90 top
C151 "Cap Pol2" CC3216-1206 285.514,250.862 r0 top
C152 "Cap Pol2" CC3216-1206 414.557,176.225 r90 top
C153 "Cap" C1608-0603 379.319,269.988 r90 top
C154 "Cap" C1608-0603 317.59,269.988 r90 top
C155 "Cap" C1608-0603 386.444,269.988 r90 top
C156 "Cap" C1608-0603 324.716,269.988 r90 top
C157 "Cap" C1608-0603 393.544,269.988 r90 top
C158 "Cap" C1608-0603 331.816,269.988 r90 top
C159 "Cap" C1608-0603 400.67,269.988 r90 top
C160 "Cap" C1608-0603 225.577,132.309 r180 bottom
C161 "Cap" C1608-0603 225.577,134.849 r180 bottom
C162 "Cap" C1608-0603 474.423,269.988 r90 top
C163 "Cap" C1608-0603 211.353,143.485 r0 bottom
C164 "Cap Pol2" CC3216-1206 210.845,140.437 r180 bottom
C165 "Cap" C1608-0603 218.059,264.795 r180 bottom
C166 "Cap" C1608-0603 262.509,158.267 r90 top
DS1 "LED2" DSO-F2/D6.1 363.793,228.786 r90 top
DS2 "LED2" DSO-F2/D6.1 369.118,228.786 r90 top
DS3 "LED2" DSO-F2/D6.1 374.968,228.786 r90 top
DS4 "LED2" DSO-F2/D6.1 380.794,228.786 r90 top
DS5 "LED2" DSO-F2/D6.1 386.644,228.786 r90 top
DS6 "LED3" "SMD _LED" 287.339,230.836 r0 top
DS7 "LED3" "SMD _LED" 293.189,230.836 r0 top
DS9 "LED3" "SMD _LED" 199.365,257.353 r0 bottom
FB1 "FB" C1608-0603 49.733,209.347 r0 bottom
FB2 "FB" C1608-0603 43.129,215.951 r0 bottom
FB3 "BLM18PG121SN1" C1608-0603 225.577,137.389 r180 bottom
J1 "Header 7X2 JTAG" HDR2X7 217.424,157.988 r0 top
J2 "352068-1" PCI2-H123 254,180.34 r270 bottom
J3 "PWP_CON" POWER_CON 164.084,268.732 r90 top
J4 "RCA" RCA 111.76,232.664 r0 top
J5 "352152-1" PCI2-H121 254,227.34 r270 bottom
JP1 "Header 2" SMA 107.696,193.04 r0 top
JP2 "Header 2" SMA 107.696,203.708 r0 top
JP3 "101_JTAG" HDR2X5 98.857,137.947 r270 top
JP4 "JTAG" HDR2X5 137.973,276.962 r0 top
JP5 "AS mode" HDR2X5 171.196,148.844 r180 top
JP6 "Header 10X2" HDR2X10 226.06,224.028 r90 top
JP7 "Header 2" SMA 107.696,214.376 r0 top
JP8 "Header 2" SMA 107.798,166.472 r0 top
JP9 "Header 2" SMA 107.925,178.308 r0 top
JP10 "Header 6X2" HDR2X6 78.74,228.092 r0 top
JP11 "Header 2X2" HDR2X2 141.021,122.707 r90 top
L1 "Inductor Iron" L44.7uH 206.248,226.06 r0 top
Q1 "QNPN3904" "SO-G3 for NPN" 155.003,242.214 r0 top
R1 "Res2" C1608-0603 25.349,240.335 r0 top
R2 "Res2" C1608-0603 115.621,274.93 r0 top
R3 "Res2" C1608-0603 114.097,276.454 r0 top
R4 "Res2" C1608-0603 28.905,236.779 r0 top
R5 "Res2" C1608-0603 32.461,238.303 r0 top
R6 "Res2" C1608-0603 30.937,239.827 r0 top
R7 "Res2" C1608-0603 32.461,232.715 r0 top
R8 "Res2" C1608-0603 135.433,132.867 r0 bottom
R9 "Res2" C1608-0603 36.525,234.747 r0 top
R10 "Res2" C1608-0603 35.001,236.271 r0 top
R11 "Res2" C1608-0603 285.239,191.434 r0 top
R12 "Res2" C1608-0603 110.007,135.077 r90 top
R13 "Res2" C1608-0603 107.467,135.077 r90 top
R14 "Res2" C1608-0603 127.305,280.518 r0 top
R15 "Res2" C1608-0603 298.715,231.086 r0 top
R16 "Res2" C1608-0603 132.385,280.518 r180 top
R17 "Res2" C1608-0603 143.053,275.438 r0 top
R18 "Res2" C1608-0603 302.79,191.434 r0 top
R19 "Res2" C1608-0603 308.39,191.434 r0 top
R20 "Res2" C1608-0603 314.615,230.186 r90 top
R21 "Res2" C1608-0603 321.341,231.086 r0 top
R22 "Res2" C1608-0603 57.556,210.363 r0 bottom
R23 "Res2" C1608-0603 57.556,212.903 r0 bottom
R24 "Res2" C1608-0603 150.368,134.62 r135 top
R25 "Res2" C1608-0603 91.44,206.756 r270 bottom
R26 "Res2" C1608-0603 188.595,162.052 r90 top
R27 "Res2" C1608-0603 58.064,215.443 r0 bottom
R28 "Res2" C1608-0603 59.385,207.823 r0 bottom
R29 "Res2" C1608-0603 40.589,225.603 r0 bottom
R30 "R0604_4" R0603_4 190.39,184.683 r0 top
R31 "R0604_4" R0603_4 201.117,164.44 r90 bottom
R32 "R0604_4" R0603_4 206.197,164.44 r90 bottom
R33 "R0604_4" R0603_4 202.641,164.44 r90 top
R34 "R0604_4" R0603_4 207.213,164.44 r90 top
R35 "R0604_4" R0603_4 191.229,184.074 r0 bottom
R36 "R0604_4" R0603_4 191.229,188.138 r0 bottom
R37 "R0604_4" R0603_4 190.39,188.747 r0 top
R38 "R0604_4" R0603_4 190.39,192.811 r0 top
R39 "Res1" CR1608-0603 442.097,269.988 r90 top
R40 "Res1" CR1608-0603 112.065,282.55 r180 top
R41 "Res1" CR1608-0603 447.947,269.988 r90 top
R42 "Res2" C1608-0603 20.218,197.409 r270 top
R43 "Res2" C1608-0603 20.218,189.789 r90 top
R44 "Res2" C1608-0603 22.25,211.633 r225 top
R45 "Res2" C1608-0603 25.857,226.111 r0 top
R46 "Res2" C1608-0603 29.921,225.095 r0 top
R47 "R0604_4" R0603_4 191.229,175.946 r0 bottom
R48 "R0604_4" R0603_4 191.229,171.882 r0 bottom
R49 "R0604_4" R0603_4 190.39,176.555 r0 top
R50 "R0604_4" R0603_4 191.567,164.871 r180 top
R51 "R0604_4" R0603_4 190.551,171.983 r0 top
R52 "R0604_4" R0603_4 191.229,180.01 r0 bottom
R53 "Res2" C1608-0603 131.826,128.88 r90 bottom
R54 "R0604_4" R0603_4 190.551,180.619 r0 top
R55 "Res1" CR1608-0603 176.454,108.941 r180 top
R56 "Res1" CR1608-0603 262.488,198.335 r90 top
R57 "Res1" CR1608-0603 268.313,198.335 r90 top
R58 "Res1" CR1608-0603 191.897,263.347 r180 top
R59 "Res1" CR1608-0603 184.48,125.451 r180 top
R60 "Res2" C1608-0603 311.912,220.98 r90 top
R61 "Res1" CR1608-0603 241.96,279.73 r0 top
R62 "Res2" CR1608-0603 174.193,297.149 r90 top
R63 "Res2" CR1608-0603 180.044,297.149 r90 top
R64 "Res1" CR1608-0603 157.81,242.214 r90 top
R65 "Res1" CR1608-0603 197.333,234.569 r0 top
R66 "Res1" CR1608-0603 197.333,237.109 r180 top
R67 "Res1" CR1608-0603 186.665,242.697 r0 top
R68 "Res1" CR1608-0603 191.237,242.697 r0 top
R69 "Res1" CR1608-0603 212.344,234.696 r0 top
R70 "Res1" CR1608-0603 186.665,239.649 r0 top
R71 "Res1" CR1608-0603 151.689,275.438 r0 bottom
R72 "Res3" CR1608-0603 156.794,238.15 r180 top
R73 "Res3" CR1608-0603 151.206,243.23 r90 top
R74 "Res1" CR1608-0603 276.714,269.988 r90 top
R76 "Res1" CR1608-0603 217.043,265.303 r270 bottom
R77 "Res2" C1608-0603 20.218,207.569 r270 top
R78 "Res1" CR1608-0603 229.235,271.907 r90 top
R79 "Res1" CR1608-0603 220.599,271.907 r0 bottom
R80 "Res1" CR1608-0603 218.465,140.945 r180 top
R81 "Res1" CR1608-0603 64.973,234.747 r0 bottom
R82 "Res1" CR1608-0603 226.06,204.216 r270 top
R83 "Res1" CR1608-0603 220.599,274.447 r0 bottom
R84 "Res1" CR1608-0603 220.599,269.367 r0 bottom
R86 "Res1" CR1608-0603 217.043,270.383 r90 bottom
R87 "Res1" CR1608-0603 230.251,280.543 r180 bottom
R88 "Res1" CR1608-0603 230.759,278.003 r180 bottom
S1 "SW DIP-2" HEADER2X2 152.908,261.62 r0 top
S2 "SW-PB" BUTTON 149.149,291.694 r270 top
U1 "TMS320DM642" GNZ548 227.584,171.704 r0 top locked
U2 "EP1C12Q240C6" PQFP240 141.224,206.248 r180 top
U3 "CYP15G0101" BGA100x10 170.688,219.964 r0 top
U4 "Oscillator   27MHz" OSC 150.368,141.224 r270 top
U5 "EPCS1SI8" SOIC8 173.736,141.732 r0 top
U6 "Oscillator   20MHz" OSC 94.488,214.884 r0 bottom
U7 "Am29LV800B" TSOP48 152.908,181.356 r270 top
U8 "HY57V283220" TSOP86 179.832,163.068 r180 top
U9 "SN74CBT16210" SSOP48 241.3,200.66 r180 bottom
U10 "SN74CBT16210" SSOP48 241.3,187.96 r180 bottom
U11 "SN74CBT16210" SSOP48 241.3,175.768 r180 top
U14 "TPS75733" SOT23-5S 165.1,242.316 r0 top
U15 "TPS54310" PWP20 201.676,232.664 r90 top
U16 "AS1117-1.5V" LM1117 139.7,245.872 r90 top
U17 "AS1117-2.5V" LM1117 128.524,245.872 r90 top
U18 "TPS3823-33" DBV5 67.462,220.777 r0 bottom
U19 "SAA7121H" QFP44_2 199.136,214.884 r0 top
U20 "ACF451832" ACF451832 218.948,214.884 r270 top
U21 "Oscillator" OSC50MHz 229.108,213.36 r0 top
U22 "93C66B" SO-G8 249.936,268.732 r0 top
U23 "Oscillator" OSC50MHz 195.961,257.759 r270 bottom

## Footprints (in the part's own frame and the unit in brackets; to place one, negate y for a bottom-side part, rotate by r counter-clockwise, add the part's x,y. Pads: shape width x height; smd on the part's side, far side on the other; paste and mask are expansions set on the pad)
0603 [mil] "for DSP"
  rect 35x30 smd: 1(0,0) 2(62.99,0)
  silkscreen extent -22,-19 84,19
ACF451832 [mm] "for ACF451832-333-T"
  rect 1.2x2.5 smd: 1(0,0) 2(2.5,0) 3(5,0)
  silkscreen extent -0.76,-1.63 5.79,1.55
BGA100x10 [mm] "for CYP15G0101"
  round 0.45 smd: A1(0,0) A2(1,0) A3(2,0) A4(3,0) A5(4,0) A6(5,0) A7(6,0) A8(7,0) A9(8,0) A10(9,0) B1(0,-1) B2(1,-1) B3(2,-1) B4(3,-1) B5(4,-1) B6(5,-1) B7(6,-1) B8(7,-1) B9(8,-1) B10(9,-1) C1(0,-2) C2(1,-2) C3(2,-2) C4(3,-2) C5(4,-2) C6(5,-2) C7(6,-2) C8(7,-2) C9(8,-2) C10(9,-2) D1(0,-3) D2(1,-3) D3(2,-3) D4(3,-3) D5(4,-3) D6(5,-3) D7(6,-3) D8(7,-3) D9(8,-3) D10(9,-3) E1(0,-4) E2(1,-4) E3(2,-4) E4(3,-4) E5(4,-4) E6(5,-4) E7(6,-4) E8(7,-4) E9(8,-4) E10(9,-4) F1(0,-5) F2(1,-5) F3(2,-5) F4(3,-5) F5(4,-5) F6(5,-5) F7(6,-5) F8(7,-5) F9(8,-5) F10(9,-5) G1(0,-6) G2(1,-6) G3(2,-6) G4(3,-6) G5(4,-6) G6(5,-6) G7(6,-6) G8(7,-6) G9(8,-6) G10(9,-6) H1(0,-7) H2(1,-7) H3(2,-7) H4(3,-7) H5(4,-7) H6(5,-7) H7(6,-7) H8(7,-7) H9(8,-7) H10(9,-7) J1(0,-8) J2(1,-8) J3(2,-8) J4(3,-8) J5(4,-8) J6(5,-8) J7(6,-8) J8(7,-8) J9(8,-8) J10(9,-8) K1(0,-9) K2(1,-9) K3(2,-9) K4(3,-9) K5(4,-9) K6(5,-9) K7(6,-9) K8(7,-9) K9(8,-9) K10(9,-9)
  silkscreen extent -1,-10 10,1
BUTTON [mm]
  rect 1.5x1.5 hole 0.9: 1(-1.27,-3.81)
  round 1.5 hole 0.9: 2(2.98,-3.81) 3(2.98,2.2) 4(-1.27,2.2)
  silkscreen extent -2.34,-4.93 4.04,3.12
C1608-0603 [mm]
  rect 1.1x1 smd: 1(-0.85,0) 2(0.85,0)
  silkscreen extent -1.8,-0.9 1.8,0.9
CC3216-1206 [mm]
  rect 1.6x1.8 smd: 1(-1.4,0) 2(1.4,0)
  silkscreen extent -2.6,-1.3 2.1,1.3
CC6032 [mm] "for 100uF"
  rect 2x3.5 smd: 1(0,0) 2(6,0)
  silkscreen extent -1.56,-2.03 7.34,2.01
CR1608-0603 [mm]
  rect 1.1x1 smd: 1(-0.85,0) 2(0.85,0)
  silkscreen extent -1.8,-0.9 1.8,0.9
DBV5 [mm] "DBV5;DBV (R-PDSO-G5);PSO;for TPS3823-33"
  rect 2x0.6 smd: 1(0,0)
  oval 2x0.6 smd: 2(0,-0.95) 3(0,-1.9) 4(3,-1.9) 5(3,0)
  silkscreen extent -1.27,-2.41 4.45,0.48
DSO-F2/D6.1 [mm]
  rect 1.5x1.5 smd: 1(-1.75,0) 2(1.75,0)
  silkscreen extent -2.9,-1.15 3.2,1.15
GNZ548 [mm] "BGA;548 Balls;Body 27 x 27 mm;for DM642"
  round 0.47 smd: A1(0,0) A2(-1,0) A3(-2,0) A4(-3,0) A5(-4,0) A6(-5,0) A7(-6,0) A8(-7,0) A9(-8,0) A10(-9,0) A11(-10,0) A12(-11,0) A13(-12,0) A14(-13,0) A15(-14,0) A16(-15,0) A17(-16,0) A18(-17,0) A19(-18,0) A20(-19,0) A21(-20,0) A22(-21,0) A23(-22,0) A24(-23,0) A25(-24,0) A26(-25,0) AA1(0,20) AA2(-1,20) AA3(-2,20) AA4(-3,20) AA5(-4,20) AA6(-5,20) AA7(-6,20) AA8(-7,20) AA9(-8,20) AA10(-9,20) AA11(-10,20) AA12(-11,20) AA13(-12,20) AA14(-13,20) AA15(-14,20) AA16(-15,20) AA17(-16,20) AA18(-17,20) AA19(-18,20) AA20(-19,20) AA21(-20,20) AA22(-21,20) AA23(-22,20) AA24(-23,20) AA25(-24,20) AA26(-25,20) AB1(0,21) AB2(-1,21) AB3(-2,21) AB4(-3,21) AB5(-4,21) AB6(-5,21) AB7(-6,21) AB8(-7,21) AB9(-8,21) AB10(-9,21) AB11(-10,21) AB12(-11,21) AB13(-12,21) AB14(-13,21) AB15(-14,21) AB16(-15,21) AB17(-16,21) AB18(-17,21) AB19(-18,21) AB20(-19,21) AB21(-20,21) AB22(-21,21) AB23(-22,21) AB24(-23,21) AB25(-24,21) AB26(-25,21) AC1(0,22) AC2(-1,22) AC3(-2,22) AC4(-3,22) AC5(-4,22) AC6(-5,22) AC7(-6,22) AC8(-7,22) AC9(-8,22) AC10(-9,22) AC11(-10,22) AC12(-11,22) AC13(-12,22) AC14(-13,22) AC15(-14,22) AC16(-15,22) AC17(-16,22) AC18(-17,22) AC19(-18,22) AC20(-19,22) AC21(-20,22) AC22(-21,22) AC23(-22,22) AC24(-23,22) AC25(-24,22) AC26(-25,22) AD1(0,23) AD2(-1,23) AD3(-2,23) AD4(-3,23) AD5(-4,23) AD6(-5,23) AD7(-6,23) AD8(-7,23) AD9(-8,23) AD10(-9,23) AD11(-10,23) AD12(-11,23) AD13(-12,23) AD14(-13,23) AD15(-14,23) AD16(-15,23) AD17(-16,23) AD18(-17,23) AD19(-18,23) AD20(-19,23) AD21(-20,23) AD22(-21,23) AD23(-22,23) AD24(-23,23) AD25(-24,23) AD26(-25,23) AE1(0,24) AE2(-1,24) AE3(-2,24) AE4(-3,24) AE5(-4,24) AE6(-5,24) AE7(-6,24) AE8(-7,24) AE9(-8,24) AE10(-9,24) AE11(-10,24) AE12(-11,24) AE13(-12,24) AE14(-13,24) AE15(-14,24) AE16(-15,24) AE17(-16,24) AE18(-17,24) AE19(-18,24) AE20(-19,24) AE21(-20,24) AE22(-21,24) AE23(-22,24) AE24(-23,24) AE25(-24,24) AE26(-25,24) AF1(0,25) AF2(-1,25) AF3(-2,25) AF4(-3,25) AF5(-4,25) AF6(-5,25) AF7(-6,25) AF8(-7,25) AF9(-8,25) AF10(-9,25) AF11(-10,25) AF12(-11,25) AF13(-12,25) AF14(-13,25) AF15(-14,25) AF16(-15,25) AF17(-16,25) AF18(-17,25) AF19(-18,25) AF20(-19,25) AF21(-20,25) AF22(-21,25) AF23(-22,25) AF24(-23,25) AF25(-24,25) AF26(-25,25) B1(0,1) B2(-1,1) B3(-2,1) B4(-3,1) B5(-4,1) B6(-5,1) B7(-6,1) B8(-7,1) B9(-8,1) B10(-9,1) B11(-10,1) B12(-11,1) B13(-12,1) B14(-13,1) B15(-14,1) B16(-15,1) B17(-16,1) B18(-17,1) B19(-18,1) B20(-19,1) B21(-20,1) B22(-21,1) B23(-22,1) B24(-23,1) B25(-24,1) B26(-25,1) C1(0,2) C2(-1,2) C3(-2,2) C4(-3,2) C5(-4,2) C6(-5,2) C7(-6,2) C8(-7,2) C9(-8,2) C10(-9,2) C11(-10,2) C12(-11,2) C13(-12,2) C14(-13,2) C15(-14,2) C16(-15,2) C17(-16,2) C18(-17,2) C19(-18,2) C20(-19,2) C21(-20,2) C22(-21,2) C23(-22,2) C24(-23,2) C25(-24,2) C26(-25,2) D1(0,3) D2(-1,3) D3(-2,3) D4(-3,3) D5(-4,3) D6(-5,3) D7(-6,3) D8(-7,3) D9(-8,3) D10(-9,3) D11(-10,3) D12(-11,3) D13(-12,3) D14(-13,3) D15(-14,3) D16(-15,3) D17(-16,3) D18(-17,3) D19(-18,3) D20(-19,3) D21(-20,3) D22(-21,3) D23(-22,3) D24(-23,3) D25(-24,3) D26(-25,3) E1(0,4) E2(-1,4) E3(-2,4) E4(-3,4) E5(-4,4) E6(-5,4) E7(-6,4) E8(-7,4) E9(-8,4) E10(-9,4) E11(-10,4) E12(-11,4) E13(-12,4) E14(-13,4) E15(-14,4) E16(-15,4) E17(-16,4) E18(-17,4) E19(-18,4) E20(-19,4) E21(-20,4) E22(-21,4) E23(-22,4) E24(-23,4) E25(-24,4) E26(-25,4) F1(0,5) F2(-1,5) F3(-2,5) F4(-3,5) F5(-4,5) F6(-5,5) F7(-6,5) F8(-7,5) F9(-8,5) F10(-9,5) F11(-10,5) F12(-11,5) F13(-12,5) F14(-13,5) F15(-14,5) F16(-15,5) F17(-16,5) F18(-17,5) F19(-18,5) F20(-19,5) F21(-20,5) F22(-21,5) F23(-22,5) F24(-23,5) F25(-24,5) F26(-25,5) G1(0,6) G2(-1,6) G3(-2,6) G4(-3,6) G5(-4,6) G6(-5,6) G7(-6,6) G8(-7,6) G9(-8,6) G10(-9,6) G11(-10,6) G12(-11,6) G13(-12,6) G14(-13,6) G15(-14,6) G16(-15,6) G17(-16,6) G18(-17,6) G19(-18,6) G20(-19,6) G21(-20,6) G22(-21,6) G23(-22,6) G24(-23,6) G25(-24,6) G26(-25,6) H1(0,7) H2(-1,7) H3(-2,7) H4(-3,7) H5(-4,7) H6(-5,7) H7(-6,7) H20(-19,7) H21(-20,7) H22(-21,7) H23(-22,7) H24(-23,7) H25(-24,7) H26(-25,7) J1(0,8) J2(-1,8) J3(-2,8) J4(-3,8) J5(-4,8) J6(-5,8) J7(-6,8) J20(-19,8) J21(-20,8) J22(-21,8) J23(-22,8) J24(-23,8) J25(-24,8) J26(-25,8) K1(0,9) K2(-1,9) K3(-2,9) K4(-3,9) K5(-4,9) K6(-5,9) K7(-6,9) K20(-19,9) K21(-20,9) K22(-21,9) K23(-22,9) K24(-23,9) K25(-24,9) K26(-25,9) L1(0,10) L2(-1,10) L3(-2,10) L4(-3,10) L5(-4,10) L6(-5,10) L7(-6,10) L20(-19,10) L21(-20,10) L22(-21,10) L23(-22,10) L24(-23,10) L25(-24,10) L26(-25,10) M1(0,11) M2(-1,11) M3(-2,11) M4(-3,11) M5(-4,11) M6(-5,11) M7(-6,11) M12(-11,11) M13(-12,11) M14(-13,11) M15(-14,11) M20(-19,11) M21(-20,11) M22(-21,11) M23(-22,11) M24(-23,11) M25(-24,11) M26(-25,11) N1(0,12) N2(-1,12) N3(-2,12) N4(-3,12) N5(-4,12) N6(-5,12) N7(-6,12) N12(-11,12) N13(-12,12) N14(-13,12) N15(-14,12) N20(-19,12) N21(-20,12) N22(-21,12) N23(-22,12) N24(-23,12) N25(-24,12) N26(-25,12) P1(0,13) P2(-1,13) P3(-2,13) P4(-3,13) P5(-4,13) P6(-5,13) P7(-6,13) P12(-11,13) P13(-12,13) P14(-13,13) P15(-14,13) P20(-19,13) P21(-20,13) P22(-21,13) P23(-22,13) P24(-23,13) P25(-24,13) P26(-25,13) R1(0,14) R2(-1,14) R3(-2,14) R4(-3,14) R5(-4,14) R6(-5,14) R7(-6,14) R12(-11,14) R13(-12,14) R14(-13,14) R15(-14,14) R20(-19,14) R21(-20,14) R22(-21,14) R23(-22,14) R24(-23,14) R25(-24,14) R26(-25,14) T1(0,15) T2(-1,15) T3(-2,15) T4(-3,15) T5(-4,15) T6(-5,15) T7(-6,15) T20(-19,15) T21(-20,15) T22(-21,15) T23(-22,15) T24(-23,15) T25(-24,15) T26(-25,15) U1(0,16) U2(-1,16) U3(-2,16) U4(-3,16) U5(-4,16) U6(-5,16) U7(-6,16) U20(-19,16) U21(-20,16) U22(-21,16) U23(-22,16) U24(-23,16) U25(-24,16) U26(-25,16) V1(0,17) V2(-1,17) V3(-2,17) V4(-3,17) V5(-4,17) V6(-5,17) V7(-6,17) V20(-19,17) V21(-20,17) V22(-21,17) V23(-22,17) V24(-23,17) V25(-24,17) V26(-25,17) W1(0,18) W2(-1,18) W3(-2,18) W4(-3,18) W5(-4,18) W6(-5,18) W7(-6,18) W20(-19,18) W21(-20,18) W22(-21,18) W23(-22,18) W24(-23,18) W25(-24,18) W26(-25,18) Y1(0,19) Y2(-1,19) Y3(-2,19) Y4(-3,19) Y5(-4,19) Y6(-5,19) Y7(-6,19) Y8(-7,19) Y9(-8,19) Y10(-9,19) Y11(-10,19) Y12(-11,19) Y13(-12,19) Y14(-13,19) Y15(-14,19) Y16(-15,19) Y17(-16,19) Y18(-17,19) Y19(-18,19) Y20(-19,19) Y21(-20,19) Y22(-21,19) Y23(-22,19) Y24(-23,19) Y25(-24,19) Y26(-25,19)
  silkscreen extent -26,-1.02 1.8,26
HDR2X2 [mm] "Connector; Header; 2x2 Position"
  rect 1.5x1.5 hole 0.9: 1(0,0)
  round 1.5 hole 0.9: 2(0,2.54) 3(2.54,0) 4(2.54,2.54)
  silkscreen extent -1.27,-1.27 3.81,3.81
HDR2X5 [mil]
  oct 62x62 hole 35: 1(0,0)
  round 62 hole 35: 2(0,100) 3(100,0) 4(100,100) 5(200,0) 6(200,100) 7(300,0) 8(300,100) 9(400,0) 10(400,100)
  silkscreen extent -50,-50 450,150
HDR2X6 [mm] "Connector; Header; 6x2 Position"
  rect 1.5x1.5 hole 0.9: 1(0,0)
  round 1.5 hole 0.9: 2(0,2.54) 3(2.54,0) 4(2.54,2.54) 5(5.08,0) 6(5.08,2.54) 7(7.62,0) 8(7.62,2.54) 9(10.16,0) 10(10.16,2.54) 11(12.7,0) 12(12.7,2.54)
  silkscreen extent -1.27,-1.27 13.97,3.81
HDR2X7 [mm] "Connector; Header; 7x2 Position"
  rect 1.5x1.5 hole 0.9: 1(0,0)
  round 1.5 hole 0.9: 2(0,2.54) 3(2.54,0) 4(2.54,2.54) 5(5.08,0) 6(5.08,2.54) 7(7.62,0) 8(7.62,2.54) 9(10.16,0) 10(10.16,2.54) 11(12.7,0) 12(12.7,2.54) 13(15.24,0) 14(15.24,2.54)
  silkscreen extent -1.27,-1.27 16.51,3.81
HDR2X10 [mm] "Connector; Header; 10x2 Position"
  rect 1.5x1.5 hole 0.9: 1(0,0)
  round 1.5 hole 0.9: 2(0,2.54) 3(2.54,0) 4(2.54,2.54) 5(5.08,0) 6(5.08,2.54) 7(7.62,0) 8(7.62,2.54) 9(10.16,0) 10(10.16,2.54) 11(12.7,0) 12(12.7,2.54) 13(15.24,0) 14(15.24,2.54) 15(17.78,0) 16(17.78,2.54) 17(20.32,0) 18(20.32,2.54) 19(22.86,0) 20(22.86,2.54)
  silkscreen extent -1.27,-1.27 24.13,3.81
HEADER2X2 [mm]
  rect 1.5x1.5 hole 0.9: 1(0,0)
  round 1.5 hole 0.9: 2(0,2.54) 3(2.54,0) 4(2.54,2.54)
  silkscreen extent -1.27,-1.27 3.81,3.81
L44.7uH [mm] "for L4"
  rect 3.5x3.5 smd: 1(0,0) 2(10,0)
  silkscreen extent -1.78,-5 11.81,5
LM1117 [mil]
  rect 90x42 smd: 1(-250,141)
  oval 90x42 smd: 2(-250,51) 3(-250,-39)
  rect 100x130 smd: 4(-20,51)
  silkscreen extent -184,-84 -85,186
OSC [mm]
  rect 2x3 smd: 1(-5,2.134) 2(-5,-2.87) 3(0,-2.866) 4(0,2.134)
  silkscreen extent -6.22,-4.52 1.19,4.48
OSC50MHz [mm] "for 50MHz"
  rect 2x3 smd: 1(-5,2.134) 2(-5,-2.87) 3(0,-2.866) 4(0,2.134)
  silkscreen extent -6.22,-4.52 1.19,4.48
PCI2-H121 [mm]
  round 1.3 hole 0.7: A1(21,-5) A2(19,-5) A3(17,-5) A4(15,-5) A5(13,-5) A6(11,-5) A7(9,-5) A8(7,-5) A9(5,-5) A10(3,-5) A11(1,-5) A12(-1,-5) A13(-3,-5) A14(-5,-5) A15(-7,-5) A16(-9,-5) A17(-11,-5) A18(-13,-5) A19(-15,-5) A20(-17,-5) A21(-19,-5) A22(-21,-5) B1(21,-3) B2(19,-3) B3(17,-3) B4(15,-3) B5(13,-3) B6(11,-3) B7(9,-3) B8(7,-3) B9(5,-3) B10(3,-3) B11(1,-3) B12(-1,-3) B13(-3,-3) B14(-5,-3) B15(-7,-3) B16(-9,-3) B17(-11,-3) B18(-13,-3) B19(-15,-3) B20(-17,-3) B21(-19,-3) B22(-21,-3) C1(21,-1) C2(19,-1) C3(17,-1) C4(15,-1) C5(13,-1) C6(11,-1) C7(9,-1) C8(7,-1) C9(5,-1) C10(3,-1) C11(1,-1) C12(-1,-1) C13(-3,-1) C14(-5,-1) C15(-7,-1) C16(-9,-1) C17(-11,-1) C18(-13,-1) C19(-15,-1) C20(-17,-1) C21(-19,-1) C22(-21,-1) D1(21,1) D2(19,1) D3(17,1) D4(15,1) D5(13,1) D6(11,1) D7(9,1) D8(7,1) D9(5,1) D10(3,1) D11(1,1) D12(-1,1) D13(-3,1) D14(-5,1) D15(-7,1) D16(-9,1) D17(-11,1) D18(-13,1) D19(-15,1) D20(-17,1) D21(-19,1) D22(-21,1) E1(21,3) E2(19,3) E3(17,3) E4(15,3) E5(13,3) E6(11,3) E7(9,3) E8(7,3) E9(5,3) E10(3,3) E11(1,3) E12(-1,3) E13(-3,3) E14(-5,3) E15(-7,3) E16(-9,3) E17(-11,3) E18(-13,3) E19(-15,3) E20(-17,3) E21(-19,3) E22(-21,3) F1(21,5) F3(17,5) F5(13,5) F7(9,5) F9(5,5) F11(1,5) F13(-3,5) F15(-7,5) F17(-11,5) F19(-15,5) F21(-19,5)
  silkscreen extent -22,-6.5 22,6.05
PCI2-H123 [mm]
  round 1.3 hole 0.7: A1(24,-5) A2(22,-5) A3(20,-5) A4(18,-5) A5(16,-5) A6(14,-5) A7(12,-5) A8(10,-5) A9(8,-5) A10(6,-5) A11(4,-5) A15(-4,-5) A16(-6,-5) A17(-8,-5) A18(-10,-5) A19(-12,-5) A20(-14,-5) A21(-16,-5) A22(-18,-5) A23(-20,-5) A24(-22,-5) A25(-24,-5) B1(24,-3) B2(22,-3) B3(20,-3) B4(18,-3) B5(16,-3) B6(14,-3) B7(12,-3) B8(10,-3) B9(8,-3) B10(6,-3) B11(4,-3) B15(-4,-3) B16(-6,-3) B17(-8,-3) B18(-10,-3) B19(-12,-3) B20(-14,-3) B21(-16,-3) B22(-18,-3) B23(-20,-3) B24(-22,-3) B25(-24,-3) C1(24,-1) C2(22,-1) C3(20,-1) C4(18,-1) C5(16,-1) C6(14,-1) C7(12,-1) C8(10,-1) C9(8,-1) C10(6,-1) C11(4,-1) C15(-4,-1) C16(-6,-1) C17(-8,-1) C18(-10,-1) C19(-12,-1) C20(-14,-1) C21(-16,-1) C22(-18,-1) C23(-20,-1) C24(-22,-1) C25(-24,-1) D1(24,1) D2(22,1) D3(20,1) D4(18,1) D5(16,1) D6(14,1) D7(12,1) D8(10,1) D9(8,1) D10(6,1) D11(4,1) D15(-4,1) D16(-6,1) D17(-8,1) D18(-10,1) D19(-12,1) D20(-14,1) D21(-16,1) D22(-18,1) D23(-20,1) D24(-22,1) D25(-24,1) E1(24,3) E2(22,3) E3(20,3) E4(18,3) E5(16,3) E6(14,3) E7(12,3) E8(10,3) E9(8,3) E10(6,3) E11(4,3) E15(-4,3) E16(-6,3) E17(-8,3) E18(-10,3) E19(-12,3) E20(-14,3) E21(-16,3) E22(-18,3) E23(-20,3) E24(-22,3) E25(-24,3) F1(24,5) F3(20,5) F5(16,5) F7(12,5) F9(8,5) F11(4,5) F13(0,5) F15(-4,5) F17(-8,5) F19(-12,5) F21(-16,5) F23(-20,5) F25(-24,5)
  silkscreen extent -25,-6.5 25,6.1
POWER_CON [mm] "for power input"
  rect 3.8x3.8 hole 2.5: 1(0,0) 2(6.5,0) 3(3.25,4.5)
  silkscreen extent -1.98,-3.56 13.31,6.78
PQFP240 [mm] "240-Pin Plastic Quad Flat Pack (PQFP)"
  rect 1.5x0.3 smd: 1(-16.975,14.75) 2(-16.975,14.25) 3(-16.975,13.75) 4(-16.975,13.25) 5(-16.975,12.75) 6(-16.975,12.25) 7(-16.975,11.75) 8(-16.975,11.25) 9(-16.975,10.75) 10(-16.975,10.25) 11(-16.975,9.75) 12(-16.975,9.25) 13(-16.975,8.75) 14(-16.975,8.25) 15(-16.975,7.75) 16(-16.975,7.25) 17(-16.975,6.75) 18(-16.975,6.25) 19(-16.975,5.75) 20(-16.975,5.25) 21(-16.975,4.75) 22(-16.975,4.25) 23(-16.975,3.75) 24(-16.975,3.25) 25(-16.975,2.75) 26(-16.975,2.25) 27(-16.975,1.75) 28(-16.975,1.25) 29(-16.975,0.75) 30(-16.975,0.25) 31(-16.975,-0.25) 32(-16.975,-0.75) 33(-16.975,-1.25) 34(-16.975,-1.75) 35(-16.975,-2.25) 36(-16.975,-2.75) 37(-16.975,-3.25) 38(-16.975,-3.75) 39(-16.975,-4.25) 40(-16.975,-4.75) 41(-16.975,-5.25) 42(-16.975,-5.75) 43(-16.975,-6.25) 44(-16.975,-6.75) 45(-16.975,-7.25) 46(-16.975,-7.75) 47(-16.975,-8.25) 48(-16.975,-8.75) 49(-16.975,-9.25) 50(-16.975,-9.75) 51(-16.975,-10.25) 52(-16.975,-10.75) 53(-16.975,-11.25) 54(-16.975,-11.75) 55(-16.975,-12.25) 56(-16.975,-12.75) 57(-16.975,-13.25) 58(-16.975,-13.75) 59(-16.975,-14.25) 60(-16.975,-14.75) 121(16.975,-14.75) 122(16.975,-14.25) 123(16.975,-13.75) 124(16.975,-13.25) 125(16.975,-12.75) 126(16.975,-12.25) 127(16.975,-11.75) 128(16.975,-11.25) 129(16.975,-10.75) 130(16.975,-10.25) 131(16.975,-9.75) 132(16.975,-9.25) 133(16.975,-8.75) 134(16.975,-8.25) 135(16.975,-7.75) 136(16.975,-7.25) 137(16.975,-6.75) 138(16.975,-6.25) 139(16.975,-5.75) 140(16.975,-5.25) 141(16.975,-4.75) 142(16.975,-4.25) 143(16.975,-3.75) 144(16.975,-3.25) 145(16.975,-2.75) 146(16.975,-2.25) 147(16.975,-1.75) 148(16.975,-1.25) 149(16.975,-0.75) 150(16.975,-0.25) 151(16.975,0.25) 152(16.975,0.75) 153(16.975,1.25) 154(16.975,1.75) 155(16.975,2.25) 156(16.975,2.75) 157(16.975,3.25) 158(16.975,3.75) 159(16.975,4.25) 160(16.975,4.75) 161(16.975,5.25) 162(16.975,5.75) 163(16.975,6.25) 164(16.975,6.75) 165(16.975,7.25) 166(16.975,7.75) 167(16.975,8.25) 168(16.975,8.75) 169(16.975,9.25) 170(16.975,9.75) 171(16.975,10.25) 172(16.975,10.75) 173(16.975,11.25) 174(16.975,11.75) 175(16.975,12.25) 176(16.975,12.75) 177(16.975,13.25) 178(16.975,13.75) 179(16.975,14.25) 180(16.975,14.75)
  rect 0.3x1.5 smd: 61(-14.75,-16.975) 62(-14.25,-16.975) 63(-13.75,-16.975) 64(-13.25,-16.975) 65(-12.75,-16.975) 66(-12.25,-16.975) 67(-11.75,-16.975) 68(-11.25,-16.975) 69(-10.75,-16.975) 70(-10.25,-16.975) 71(-9.75,-16.975) 72(-9.25,-16.975) 73(-8.75,-16.975) 74(-8.25,-16.975) 75(-7.75,-16.975) 76(-7.25,-16.975) 77(-6.75,-16.975) 78(-6.25,-16.975) 79(-5.75,-16.975) 80(-5.25,-16.975) 81(-4.75,-16.975) 82(-4.25,-16.975) 83(-3.75,-16.975) 84(-3.25,-16.975) 85(-2.75,-16.975) 86(-2.25,-16.975) 87(-1.75,-16.975) 88(-1.25,-16.975) 89(-0.75,-16.975) 90(-0.25,-16.975) 91(0.25,-16.975) 92(0.75,-16.975) 93(1.25,-16.975) 94(1.75,-16.975) 95(2.25,-16.975) 96(2.75,-16.975) 97(3.25,-16.975) 98(3.75,-16.975) 99(4.25,-16.975) 100(4.75,-16.975) 101(5.25,-16.975) 102(5.75,-16.975) 103(6.25,-16.975) 104(6.75,-16.975) 105(7.25,-16.975) 106(7.75,-16.975) 107(8.25,-16.975) 108(8.75,-16.975) 109(9.25,-16.975) 110(9.75,-16.975) 111(10.25,-16.975) 112(10.75,-16.975) 113(11.25,-16.975) 114(11.75,-16.975) 115(12.25,-16.975) 116(12.75,-16.975) 117(13.25,-16.975) 118(13.75,-16.975) 119(14.25,-16.975) 120(14.75,-16.975) 181(14.75,16.975) 182(14.25,16.975) 183(13.75,16.975) 184(13.25,16.975) 185(12.75,16.975) 186(12.25,16.975) 187(11.75,16.975) 188(11.25,16.975) 189(10.75,16.975) 190(10.25,16.975) 191(9.75,16.975) 192(9.25,16.975) 193(8.75,16.975) 194(8.25,16.975) 195(7.75,16.975) 196(7.25,16.975) 197(6.75,16.975) 198(6.25,16.975) 199(5.75,16.975) 200(5.25,16.975) 201(4.75,16.975) 202(4.25,16.975) 203(3.75,16.975) 204(3.25,16.975) 205(2.75,16.975) 206(2.25,16.975) 207(1.75,16.975) 208(1.25,16.975) 209(0.75,16.975) 210(0.25,16.975) 211(-0.25,16.975) 212(-0.75,16.975) 213(-1.25,16.975) 214(-1.75,16.975) 215(-2.25,16.975) 216(-2.75,16.975) 217(-3.25,16.975) 218(-3.75,16.975) 219(-4.25,16.975) 220(-4.75,16.975) 221(-5.25,16.975) 222(-5.75,16.975) 223(-6.25,16.975) 224(-6.75,16.975) 225(-7.25,16.975) 226(-7.75,16.975) 227(-8.25,16.975) 228(-8.75,16.975) 229(-9.25,16.975) 230(-9.75,16.975) 231(-10.25,16.975) 232(-10.75,16.975) 233(-11.25,16.975) 234(-11.75,16.975) 235(-12.25,16.975) 236(-12.75,16.975) 237(-13.25,16.975) 238(-13.75,16.975) 239(-14.25,16.975) 240(-14.75,16.975)
  silkscreen extent -17.1,-15.83 15.83,15.83
PWP20 [mm] "PWP20;PSO;PWP (R-PDSO-G**);for TPS54310"
  rect 2x0.4 smd: 1(0,0)
  rect 2.032x3.81 smd: 1(3.302,-2.921)
  oval 2x0.4 smd: 2(0,-0.65) 3(0,-1.3) 4(0,-1.95) 5(0,-2.6) 6(0,-3.25) 7(0,-3.9) 8(0,-4.55) 9(0,-5.2) 10(0,-5.85)
  oval 2.2x0.4 smd: 11(6.6,-5.85) 12(6.6,-5.2) 13(6.6,-4.55) 14(6.6,-3.9) 15(6.6,-3.25) 16(6.6,-2.6) 17(6.6,-1.95) 18(6.6,-1.3) 19(6.6,-0.65) 20(6.6,0)
  silkscreen extent 2.08,-6.18 4.51,0.33
QFP44_2 [mm]
  oval 2.5x0.4 smd: 1(0,0)
  rect 2.5x0.4 smd: 2(0,-0.8) 3(0,-1.6) 4(0,-2.4) 5(0,-3.2) 6(0,-4) 7(0,-4.8) 8(0,-5.6) 9(0,-6.4) 10(0,-7.2) 11(0,-8) 23(12.9,-8) 24(12.9,-7.2) 25(12.9,-6.4) 26(12.9,-5.6) 27(12.9,-4.8) 28(12.9,-4) 29(12.9,-3.2) 30(12.9,-2.4) 31(12.9,-1.6) 32(12.9,-0.8) 33(12.9,0)
  rect 0.4x2.5 smd: 12(2.45,-10.45) 13(3.25,-10.45) 14(4.05,-10.45) 15(4.85,-10.45) 16(5.65,-10.45) 17(6.45,-10.45) 18(7.25,-10.45) 19(8.05,-10.45) 20(8.85,-10.45) 21(9.65,-10.45) 22(10.45,-10.45) 34(10.45,2.45) 35(9.65,2.45) 36(8.85,2.45) 37(8.05,2.45) 38(7.25,2.45) 39(6.45,2.45) 40(5.65,2.45) 41(4.85,2.45) 42(4.05,2.45) 43(3.25,2.45) 44(2.45,2.45)
  silkscreen extent 1.78,-8.67 11.12,0.66
R0603_4 [mil] "for ResPackX4____OK!"
  rect 35x18 smd: 1(0,0) 2(0,-36) 3(0,-72) 4(0,-108) 5(70.16,-108) 6(70.16,-72) 7(70.16,-36) 8(70.16,0)
  silkscreen extent -33,-123 99,15
RCA [mm]
  round 3.5 hole 2.1: 1(4.433,-1.168) 1(4.433,2.832) 2(-1.067,-1.168)
  silkscreen extent -6.91,-6.2 6.43,4.83
SMA [mm]
  round 3 hole 1.8: 1(0,0) 2(-2.5,-2.5) 2(-2.5,2.5) 2(2.5,-2.5) 2(2.5,2.5)
  silkscreen extent -4.5,-4.8 4.5,4.6
"SMD _LED" [mm]
  rect 1.3x1.6 smd: 1(0.95,0) 2(-0.95,0)
  silkscreen extent -2.13,-1.15 2,1.15
"SO-G3 for NPN" [mm]
  rect 0.9x1.27 smd: 1(0,1.25)
  rect 0.9x0.95 smd: 2(-0.95,-1.25) 3(0.95,-1.25)
  silkscreen extent -2.07,-1.37 1.3,1.25
SO-G8 [mm]
  rect 0.6x2.2 smd: 1(-1.905,-2.6) 2(-0.635,-2.6) 3(0.635,-2.6) 4(1.905,-2.6) 5(1.905,2.6) 6(0.635,2.6) 7(-0.635,2.6) 8(-1.905,2.6)
  silkscreen extent -2.88,-2.72 2.5,1.1
SOIC8 [mm] "8-Pin Small-Outline Integrated Circuit (SOIC)"
  rect 0.6x2.2 smd: 1(-1.905,-2.6) 2(-0.635,-2.6) 3(0.635,-2.6) 4(1.905,-2.6) 5(1.905,2.6) 6(0.635,2.6) 7(-0.635,2.6) 8(-1.905,2.6)
  silkscreen extent -2.88,-2.72 2.5,1.1
SOT23-5S [mil] "for TPS75733"
  oval 200x50 smd: 1(0,0) 2(0,-67) 3(0,-134) 4(0,-201) 5(0,-268)
  rect 400x400 smd: 3(375,-135)
  silkscreen extent 130,-360 580,95
SSOP48 [mm]
  rect 2x0.28 smd: 1(0,0)
  oval 2x0.28 smd: 2(0,-0.5) 3(0,-1) 4(0,-1.5) 5(0,-2) 6(0,-2.5) 7(0,-3) 8(0,-3.5) 9(0,-4) 10(0,-4.5) 11(0,-5) 12(0,-5.5) 13(0,-6) 14(0,-6.5) 15(0,-7) 16(0,-7.5) 17(0,-8) 18(0,-8.5) 19(0,-9) 20(0,-9.5) 21(0,-10) 22(0,-10.5) 23(0,-11) 24(0,-11.5) 25(8,-11.5) 26(8,-11) 27(8,-10.5) 28(8,-10) 29(8,-9.5) 30(8,-9) 31(8,-8.5) 32(8,-8) 33(8,-7.5) 34(8,-7) 35(8,-6.5) 36(8,-6) 37(8,-5.5) 38(8,-5) 39(8,-4.5) 40(8,-4) 41(8,-3.5) 42(8,-3) 43(8,-2.5) 44(8,-2) 45(8,-1.5) 46(8,-1) 47(8,-0.5) 48(8,0)
  silkscreen extent 1.84,-11.75 6.16,0.25
TSOP48 [mm] "for Am29LV800B"
  rect 2x0.3 smd: 1(0,0)
  oval 2x0.3 smd: 2(0,-0.5) 3(0,-1) 4(0,-1.5) 5(0,-2) 6(0,-2.5) 7(0,-3) 8(0,-3.5) 9(0,-4) 10(0,-4.5) 11(0,-5) 12(0,-5.5) 13(0,-6) 14(0,-6.5) 15(0,-7) 16(0,-7.5) 17(0,-8) 18(0,-8.5) 19(0,-9) 20(0,-9.5) 21(0,-10) 22(0,-10.5) 23(0,-11) 24(0,-11.5) 25(20.2,-11.5) 26(20.2,-11) 27(20.2,-10.5) 28(20.2,-10) 29(20.2,-9.5) 30(20.2,-9) 31(20.2,-8.5) 32(20.2,-8) 33(20.2,-7.5) 34(20.2,-7) 35(20.2,-6.5) 36(20.2,-6) 37(20.2,-5.5) 38(20.2,-5) 39(20.2,-4.5) 40(20.2,-4) 41(20.2,-3.5) 42(20.2,-3) 43(20.2,-2.5) 44(20.2,-2) 45(20.2,-1.5) 46(20.2,-1) 47(20.2,-0.5) 48(20.2,0)
  silkscreen extent 2.08,-11.75 18.12,0.25
TSOP86 [mm] "TSOP;43*2;for HY57V283220"
  rect 2x0.3 smd: 1(0,0)
  oval 2x0.3 smd: 2(0,-0.5) 3(0,-1) 4(0,-1.5) 5(0,-2) 6(0,-2.5) 7(0,-3) 8(0,-3.5) 9(0,-4) 10(0,-4.5) 11(0,-5) 12(0,-5.5) 13(0,-6) 14(0,-6.5) 15(0,-7) 16(0,-7.5) 17(0,-8) 18(0,-8.5) 19(0,-9) 20(0,-9.5) 21(0,-10) 22(0,-10.5) 23(0,-11) 24(0,-11.5) 25(0,-12) 26(0,-12.5) 27(0,-13) 28(0,-13.5) 29(0,-14) 30(0,-14.5) 31(0,-15) 32(0,-15.5) 33(0,-16) 34(0,-16.5) 35(0,-17) 36(0,-17.5) 37(0,-18) 38(0,-18.5) 39(0,-19) 40(0,-19.5) 41(0,-20) 42(0,-20.5) 43(0,-21) 44(11.938,-21) 45(11.938,-20.5) 46(11.938,-20) 47(11.938,-19.5) 48(11.938,-19) 49(11.938,-18.5) 50(11.938,-18) 51(11.938,-17.5) 52(11.938,-17) 53(11.938,-16.5) 54(11.938,-16) 55(11.938,-15.5) 56(11.938,-15) 57(11.938,-14.5) 58(11.938,-14) 59(11.938,-13.5) 60(11.938,-13) 61(11.938,-12.5) 62(11.938,-12) 63(11.938,-11.5) 64(11.938,-11) 65(11.938,-10.5) 66(11.938,-10) 67(11.938,-9.5) 68(11.938,-9) 69(11.938,-8.5) 70(11.938,-8) 71(11.938,-7.5) 72(11.938,-7) 73(11.938,-6.5) 74(11.938,-6) 75(11.938,-5.5) 76(11.938,-5) 77(11.938,-4.5) 78(11.938,-4) 79(11.938,-3.5) 80(11.938,-3) 81(11.938,-2.5) 82(11.938,-2) 83(11.938,-1.5) 84(11.938,-1) 85(11.938,-0.5) 86(11.938,0)
  silkscreen extent -0.23,-21.25 9.85,0.73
